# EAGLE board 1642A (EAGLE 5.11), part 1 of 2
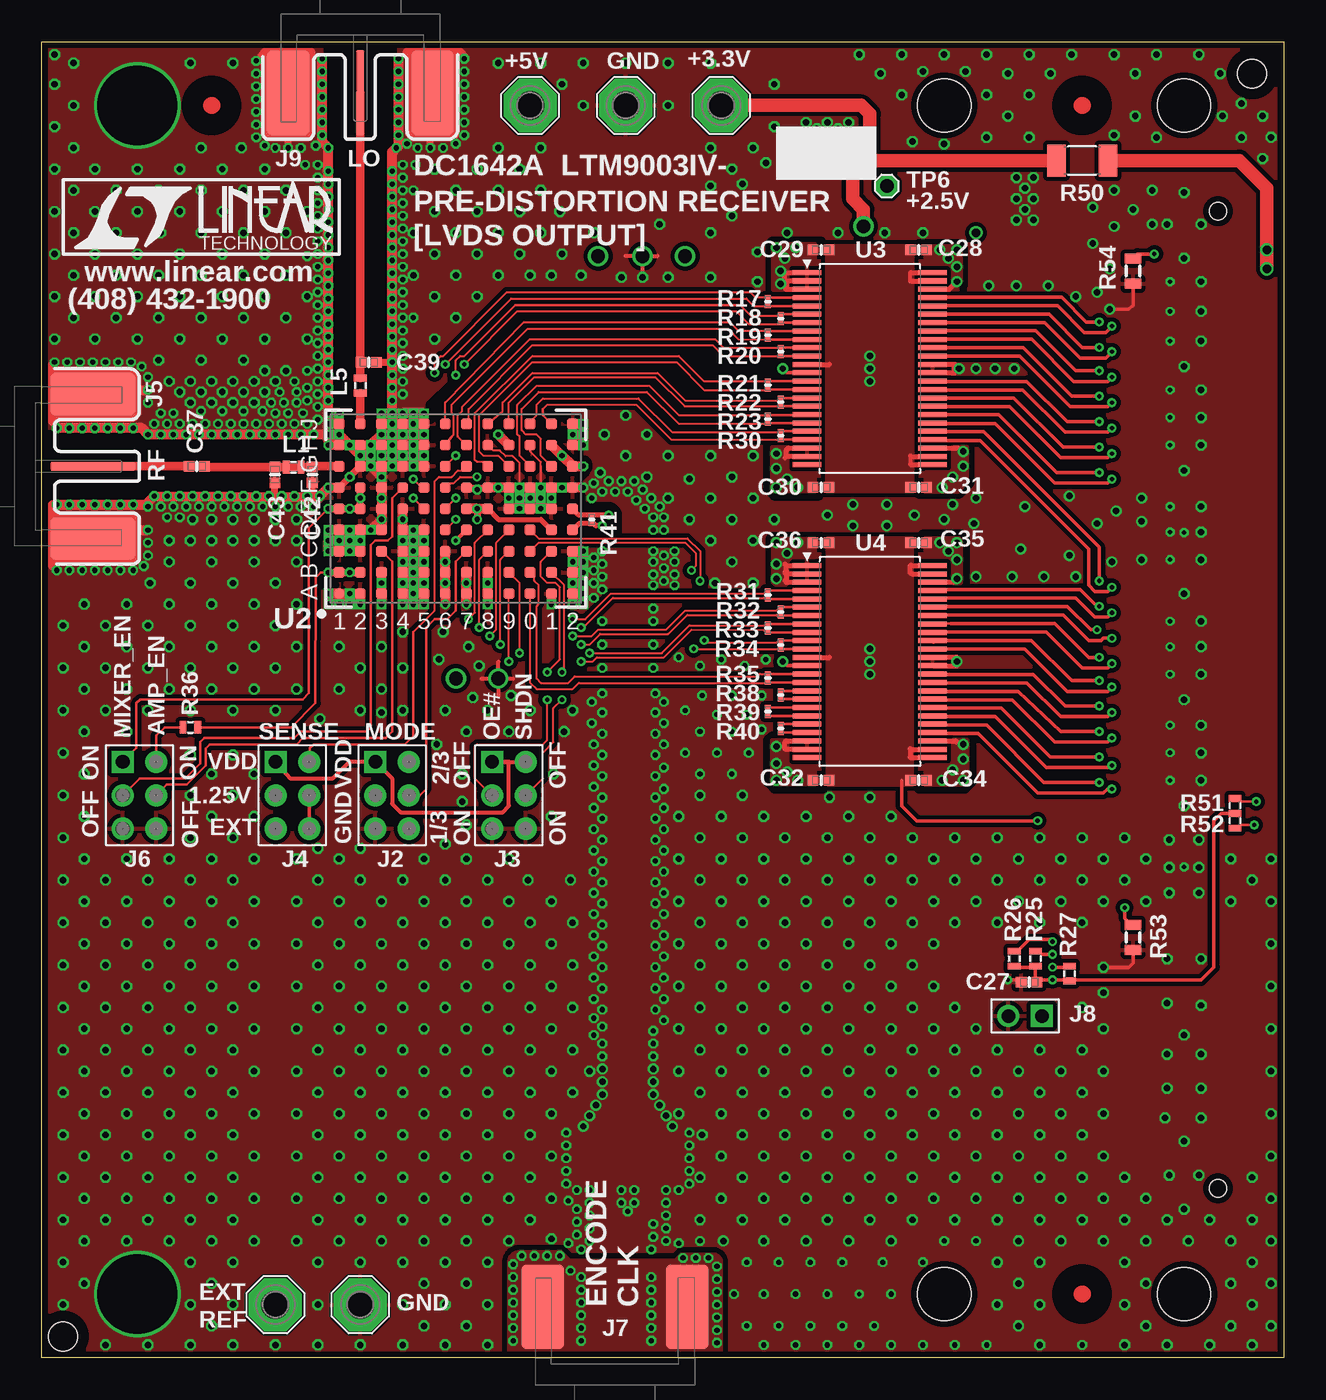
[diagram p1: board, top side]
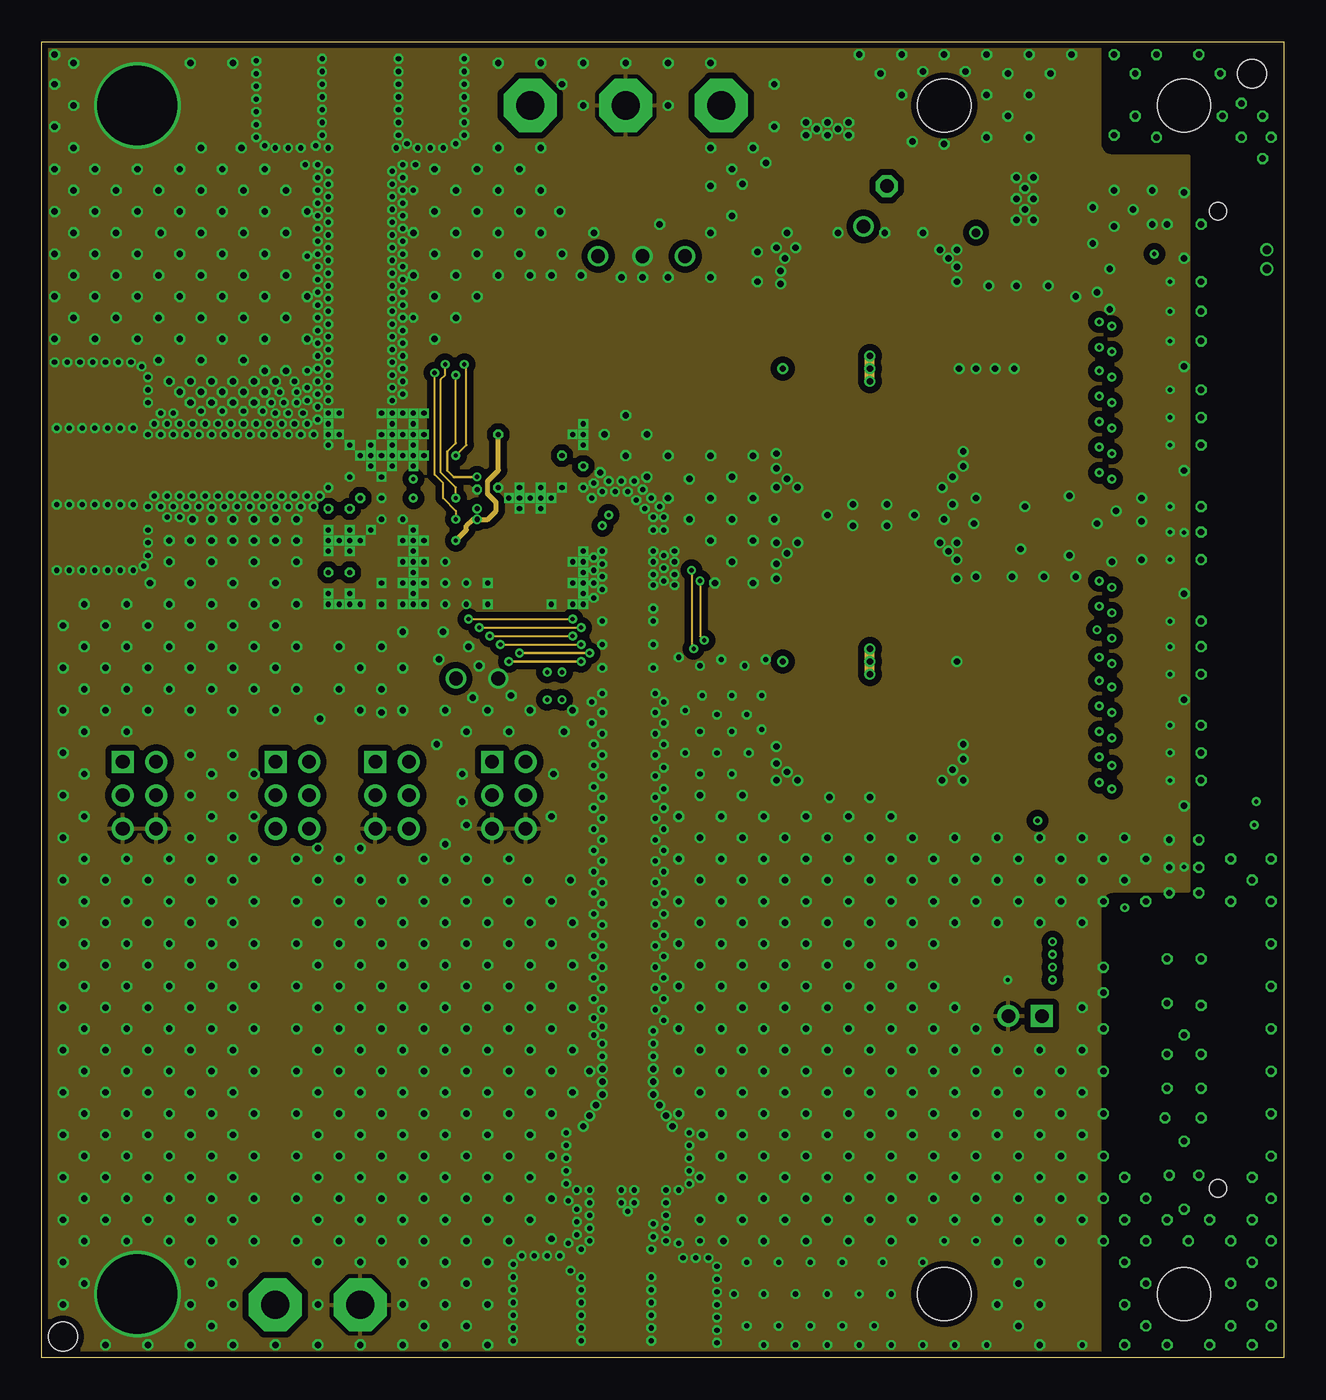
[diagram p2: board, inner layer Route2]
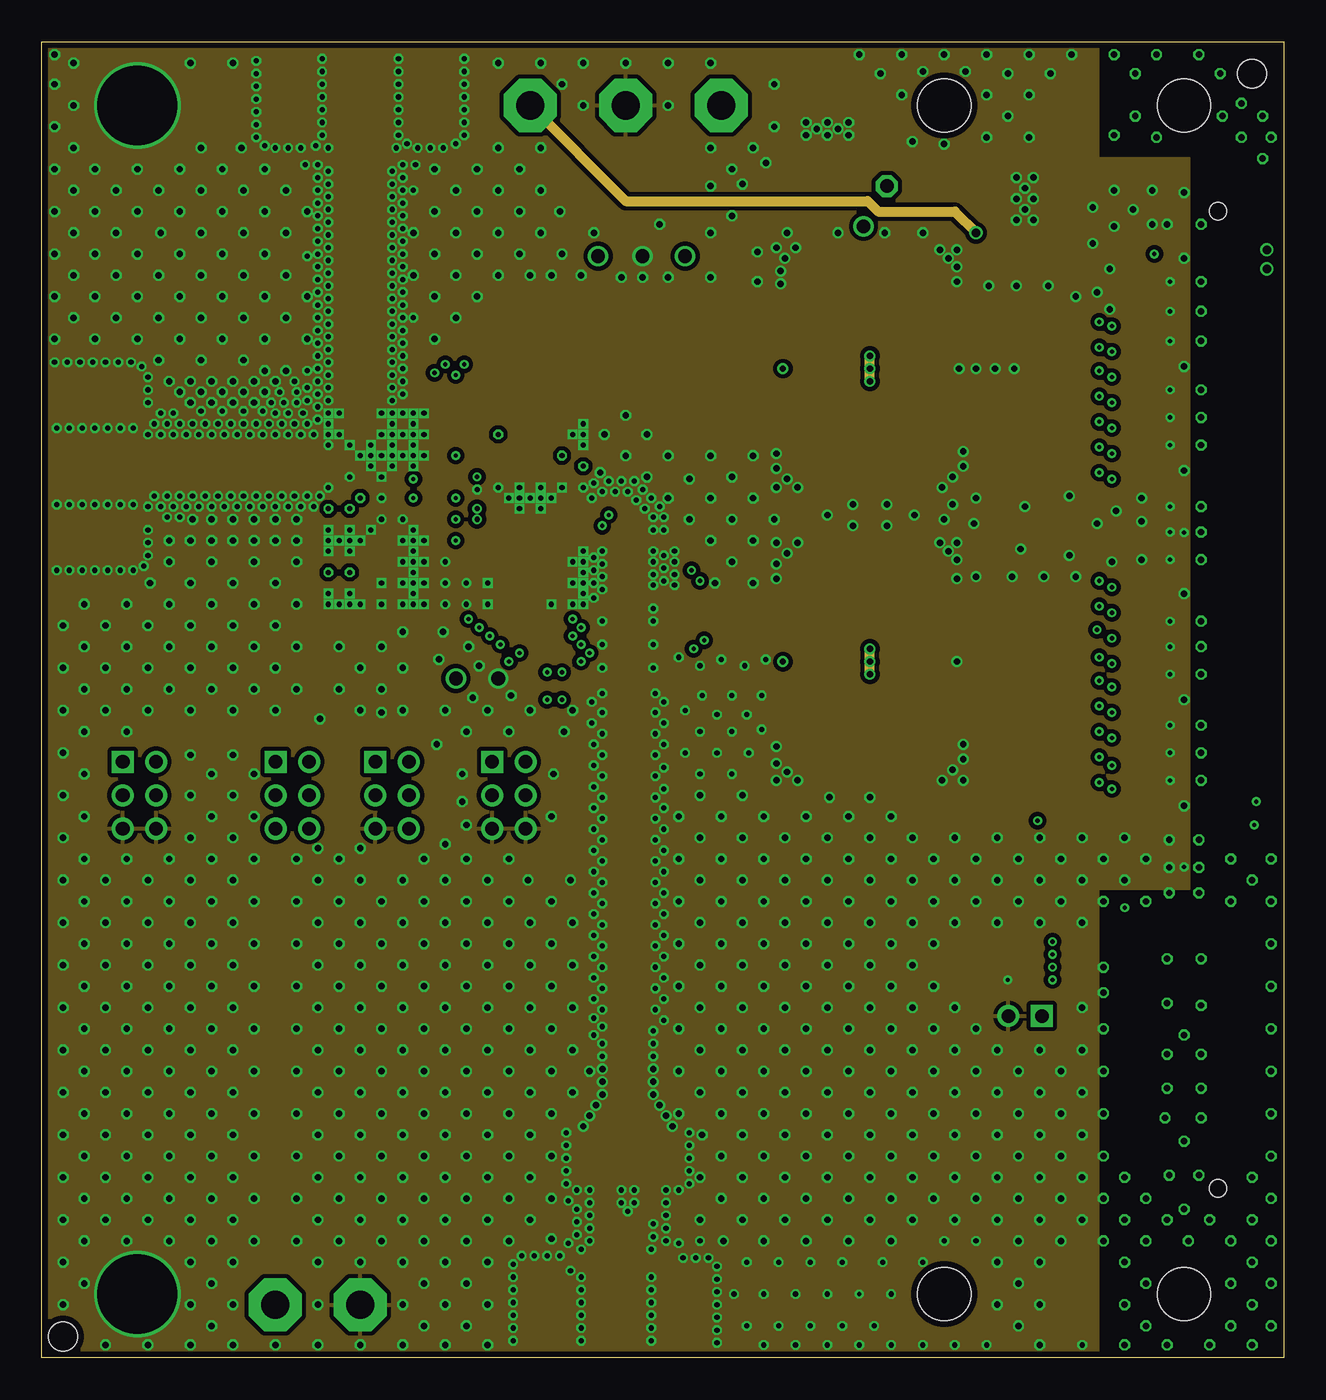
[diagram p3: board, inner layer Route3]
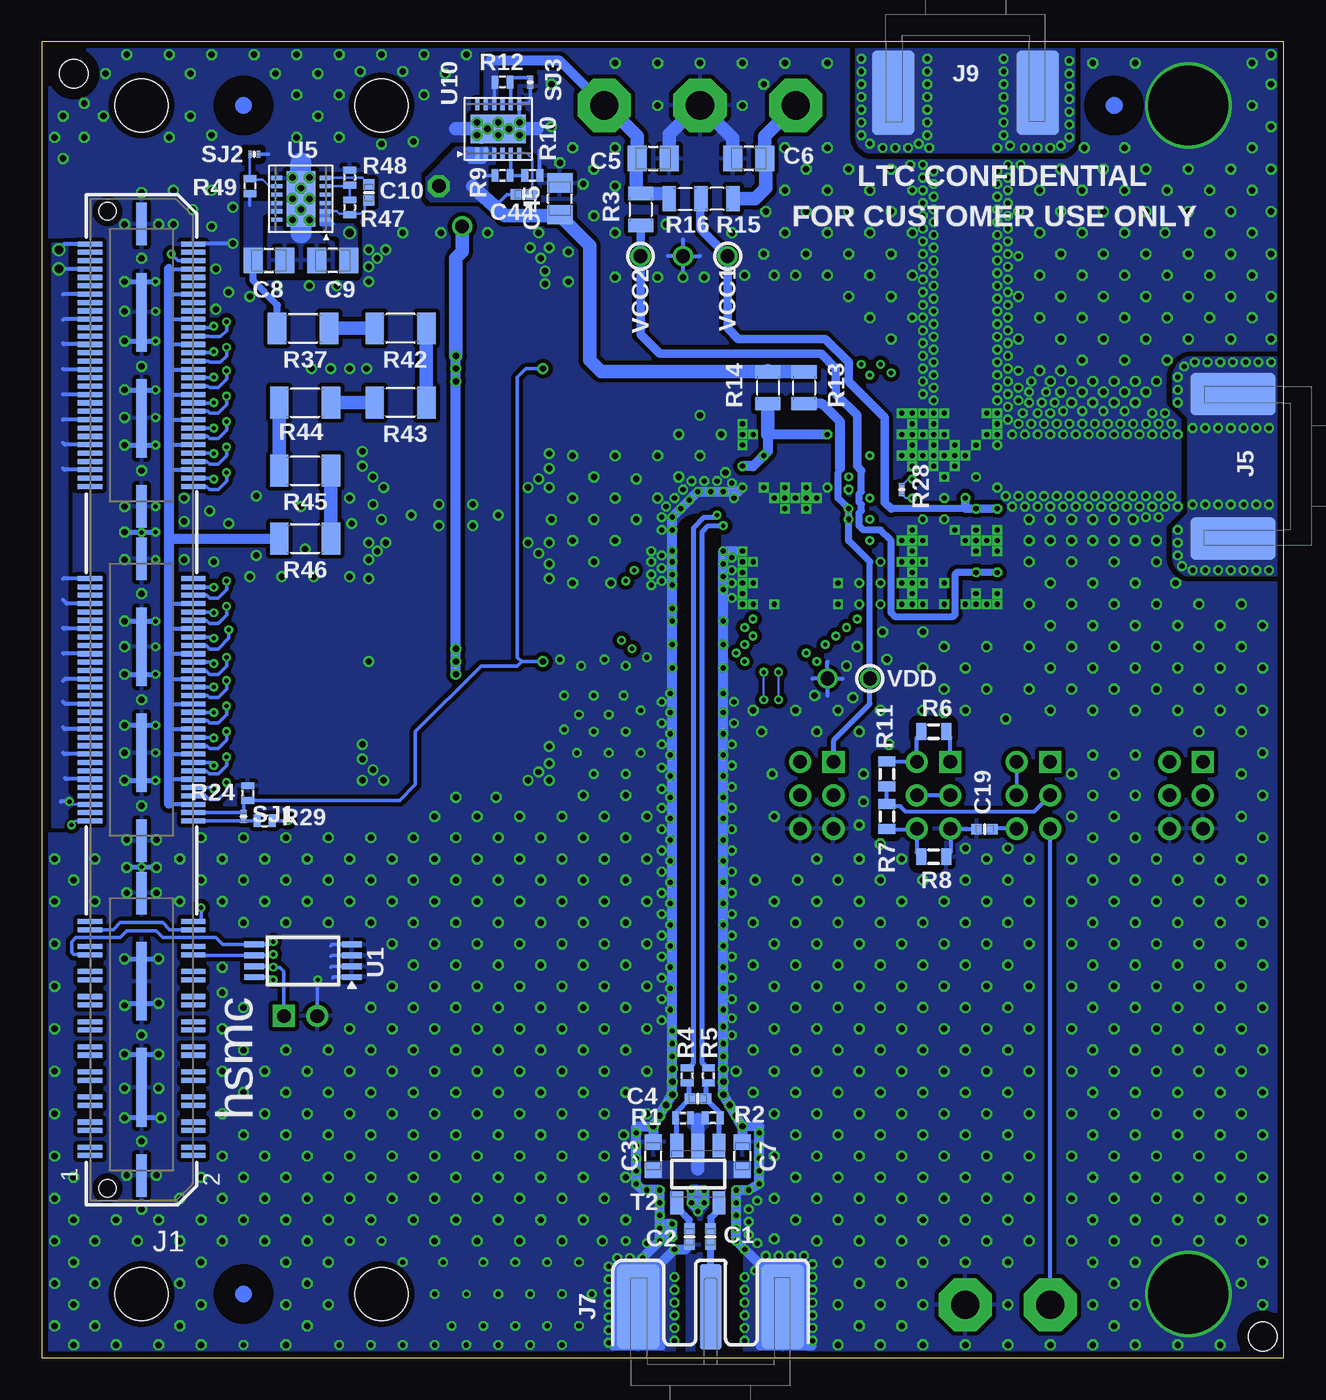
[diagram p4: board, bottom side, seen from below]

Size 74.3 x 78.74 mm. Coordinates in mm from the lower left corner, seen from the top.
Outline: 74.3,6.98 74.3,0 0,0 0,78.74 74.3,78.74 74.3,6.98
Outline: 74.3,6.98 74.3,6.73
Copper layers (1+2*3+16): Top 0.035mm / dielectric 0.28mm / Route2 0.035mm / dielectric 0.7mm / Route3 0.035mm / dielectric 0.28mm / Bottom 0.035mm
Design rules "tight_with_rnding_err_tol": minimum track width 5mil, minimum drill 10mil, track to track 5mil, track to pad 5mil, pad to pad 5mil, via to via 5mil, smd to smd 0mil, copper to edge 15mil, drill to drill 12mil, minimum pad ring 10mil, minimum via ring 0.1372mm, stop-mask expansion 3mil, vias tented up to drill 16mil, thermal gap 10mil
tRestrict: area 35.4,65.4 to 36.5,66.4; area 26.8,40.1 to 27.8,41.1; 96 lines
bRestrict: area 35.4,65.4 to 36.4,66.4; area 26.8,40.1 to 27.8,41.1; 56 lines

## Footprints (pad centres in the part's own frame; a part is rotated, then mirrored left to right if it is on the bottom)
C0402 = smd 0.635 x 0.635: 1 -0.472,0; 2 0.472,0
C0603 = smd 0.914 x 1.016: 1 -0.837,0; 2 0.837,0
C0805 = smd 1.143 x 1.524: 1 -0.952,0; 2 0.952,0
HSMC_ASP-122952-01_MEZZANINECARD = smd 0.305 x 1.448: 1 -27.271,3.086; 2 -27.271,-3.086; 3 -26.77,3.086; 4 -26.77,-3.086; 5 -25.77,3.086; 6 -25.77,-3.086; 7 -25.269,3.086; 8 -25.269,-3.086; 9 -24.268,3.086; 10 -24.268,-3.086; 11 -23.768,3.086; 12 -23.768,-3.086; 13 -22.767,3.086; 14 -22.767,-3.086; 15 -22.267,3.086; 16 -22.267,-3.086; 17 -21.266,3.086; 18 -21.266,-3.086; 19 -20.766,3.086; 20 -20.766,-3.086; 21 -19.765,3.086; 22 -19.765,-3.086; 23 -19.265,3.086; 24 -19.265,-3.086; 25 -18.264,3.086; 26 -18.264,-3.086; 27 -17.764,3.086; 28 -17.764,-3.086; 29 -16.763,3.086; 30 -16.763,-3.086; 31 -16.262,3.086; 32 -16.262,-3.086; 33 -15.262,3.086; 34 -15.262,-3.086; 35 -14.761,3.086; 36 -14.761,-3.086; 37 -13.76,3.086; 38 -13.76,-3.086; 39 -13.26,3.086; 40 -13.26,-3.086; 41 -7.255,3.086; 42 -7.255,-3.086; 43 -6.755,3.086; 44 -6.755,-3.086; 45 -6.255,3.086; 46 -6.255,-3.086; 47 -5.754,3.086; 48 -5.754,-3.086; 49 -5.254,3.086; 50 -5.254,-3.086; 51 -4.754,3.086; 52 -4.754,-3.086; 53 -4.253,3.086; 54 -4.253,-3.086; 55 -3.753,3.086; 56 -3.753,-3.086; 57 -3.252,3.086; 58 -3.252,-3.086; 59 -2.752,3.086; 60 -2.752,-3.086; 61 -2.252,3.086; 62 -2.252,-3.086; 63 -1.751,3.086; 64 -1.751,-3.086; 65 -1.251,3.086; 66 -1.251,-3.086; 67 -0.75,3.086; 68 -0.75,-3.086; 69 -0.25,3.086; 70 -0.25,-3.086; 71 0.25,3.086; 72 0.25,-3.086; 73 0.751,3.086; 74 0.751,-3.086; 75 1.251,3.086; 76 1.251,-3.086; 77 1.751,3.086; 78 1.751,-3.086; 79 2.252,3.086; 80 2.252,-3.086; 81 2.752,3.086; 82 2.752,-3.086; 83 3.252,3.086; 84 3.252,-3.086; 85 3.753,3.086; 86 3.753,-3.086; 87 4.253,3.086; 88 4.253,-3.086; 89 4.754,3.086; 90 4.754,-3.086; 91 5.254,3.086; 92 5.254,-3.086; 93 5.754,3.086; 94 5.754,-3.086; 95 6.255,3.086; 96 6.255,-3.086; 97 6.755,3.086; 98 6.755,-3.086; 99 7.255,3.086; 100 7.255,-3.086; 101 12.76,3.086; 102 12.76,-3.086; 103 13.26,3.086; 104 13.26,-3.086; 105 13.761,3.086; 106 13.761,-3.086; 107 14.261,3.086; 108 14.261,-3.086; 109 14.761,3.086; 110 14.761,-3.086; 111 15.262,3.086; 112 15.262,-3.086; 113 15.762,3.086; 114 15.762,-3.086; 115 16.262,3.086; 116 16.262,-3.086; 117 16.763,3.086; 118 16.763,-3.086; 119 17.263,3.086; 120 17.263,-3.086; 121 17.764,3.086; 122 17.764,-3.086; 123 18.264,3.086; 124 18.264,-3.086; 125 18.764,3.086; 126 18.764,-3.086; 127 19.265,3.086; 128 19.265,-3.086; 129 19.765,3.086; 130 19.765,-3.086; 131 20.265,3.086; 132 20.265,-3.086; 133 20.766,3.086; 134 20.766,-3.086; 135 21.266,3.086; 136 21.266,-3.086; 137 21.767,3.086; 138 21.767,-3.086; 139 22.267,3.086; 140 22.267,-3.086; 141 22.767,3.086; 142 22.767,-3.086; 143 23.268,3.086; 144 23.268,-3.086; 145 23.768,3.086; 146 23.768,-3.086; 147 24.268,3.086; 148 24.268,-3.086; 149 24.769,3.086; 150 24.769,-3.086; 151 25.269,3.086; 152 25.269,-3.086; 153 25.77,3.086; 154 25.77,-3.086; 155 26.27,3.086; 156 26.27,-3.086; 157 26.77,3.086; 158 26.77,-3.086; 159 27.271,3.086; 160 27.271,-3.086 | smd 2.54 x 0.635: G1 -28.461,0; G4 -11.57,0; G5 -8.445,0; G8 8.445,0; G9 11.57,0; G12 28.461,0 | smd 4.699 x 0.635: G2 -23.191,0; G3 -16.841,0; G6 -3.176,0; G7 3.174,0; G10 16.839,0; G11 23.189,0 | hole 3.175: -35.56,0; 35.56,0; -35.56,-14.351; 35.56,-14.351 | hole 1.016: -29.235,2.032; 29.235,2.032
HDR-3X2PS-2MM = drill 0.813 square: 1 -2,-1 | drill 0.813 round: 2 -2,1; 3 0,-1; 4 0,1; 5 2,-1; 6 2,1
SMA_FEMALE_EDGE_MNT_GHZ = smd 5.08 x 0.508: 1 3.048,0 | smd 5.08 x 2.54: 2 3.048,4.318; 3 3.048,-4.318 | smd 5.08 x 2.54 bottom: 4 3.048,4.318; 5 3.048,-4.318
SMA-FEMALE-EDGE-MNT = smd 5.08 x 1.27: 1 3.048,0 | smd 5.08 x 2.54: 2 3.048,4.318; 3 3.048,-4.318 | smd 5.08 x 2.54 bottom: 4 3.048,4.318; 5 3.048,-4.318
HDR-2X1PS-2MM = drill 0.813 square: 1 0,0 | drill 0.813 round: 2 2,0
L0402 = smd 0.406 x 0.762: 1 -0.447,0; 2 0.447,0
R0402 = smd 0.406 x 0.762: 1 -0.447,0; 2 0.447,0
R0805 = smd 0.8 x 1.5: 1 -0.951,0; 2 0.951,0
R0603 = smd 0.6 x 1: 1 -0.75,0; 2 0.75,0
R0201 = smd 0.279 x 0.432: 1 -0.254,0; 2 0.254,0
R1206 = smd 1.1 x 1.9: 1 -1.547,0; 2 1.547,0
SJ1 = smd 0.279 x 0.432: 1 -0.254,0; 2 0.254,0
MACOM_ETC1-XFMR = smd 0.762 x 1.397: 1 0,0; 2 1.27,0; 3 2.54,0; 4 2.54,-3.429; 5 0,-3.429
TURRET_MILLMAX_2308-2 = drill 1.676 pad 3.175 octagon: 1 0,0
VIA-25MIL = drill 0.813 pad 1.143 octagon: 1 0,0
TSSOP8 = smd 0.35 x 1.2: 1 -0.975,-2.925; 2 -0.325,-2.925; 3 0.325,-2.925; 4 0.975,-2.925; 5 0.975,2.925; 6 0.325,2.925; 7 -0.325,2.925; 8 -0.975,2.925
LTM9003-RNDED = smd 0.635 x 0.635: A1 -6.985,-5.08; A2 -5.715,-5.08; A3 -4.445,-5.08; A4 -3.175,-5.08; A5 -1.905,-5.08; A6 -0.635,-5.08; A7 0.635,-5.08; A8 1.905,-5.08; A9 3.175,-5.08; A10 4.445,-5.08; A11 5.715,-5.08; A12 6.985,-5.08; B1 -6.985,-3.81; B2 -5.715,-3.81; B3 -4.445,-3.81; B4 -3.175,-3.81; B5 -1.905,-3.81; B6 -0.635,-3.81; B7 0.635,-3.81; B8 1.905,-3.81; B9 3.175,-3.81; B10 4.445,-3.81; B11 5.715,-3.81; B12 6.985,-3.81; C1 -6.985,-2.54; C2 -5.715,-2.54; C3 -4.445,-2.54; C4 -3.175,-2.54; C5 -1.905,-2.54; C6 -0.635,-2.54; C7 0.635,-2.54; C8 1.905,-2.54; C9 3.175,-2.54; C10 4.445,-2.54; C11 5.715,-2.54; C12 6.985,-2.54; D1 -6.985,-1.27; D2 -5.715,-1.27; D3 -4.445,-1.27; D4 -3.175,-1.27; D5 -1.905,-1.27; D6 -0.635,-1.27; D7 0.635,-1.27; D8 1.905,-1.27; D9 3.175,-1.27; D10 4.445,-1.27; D11 5.715,-1.27; D12 6.985,-1.27; E1 -6.985,0; E2 -5.715,0; E3 -4.445,0; E4 -3.175,0; E5 -1.905,0; E6 -0.635,0; E7 0.635,0; E8 1.905,0; E9 3.175,0; E10 4.445,0; E11 5.715,0; E12 6.985,0; F1 -6.985,1.27; F2 -5.715,1.27; F3 -4.445,1.27; F4 -3.175,1.27; F5 -1.905,1.27; F6 -0.635,1.27; F7 0.635,1.27; F8 1.905,1.27; F9 3.175,1.27; F10 4.445,1.27; F11 5.715,1.27; F12 6.985,1.27; G1 -6.985,2.54; G2 -5.715,2.54; G3 -4.445,2.54; G4 -3.175,2.54; G5 -1.905,2.54; G6 -0.635,2.54; G7 0.635,2.54; G8 1.905,2.54; G9 3.175,2.54; G10 4.445,2.54; G11 5.715,2.54; G12 6.985,2.54; H1 -6.985,3.81; H2 -5.715,3.81; H3 -4.445,3.81; H4 -3.175,3.81; H5 -1.905,3.81; H6 -0.635,3.81; H7 0.635,3.81; H8 1.905,3.81; H9 3.175,3.81; H10 4.445,3.81; H11 5.715,3.81; H12 6.985,3.81; J1 -6.985,5.08; J2 -5.715,5.08; J3 -4.445,5.08; J4 -3.175,5.08; J5 -1.905,5.08; J6 -0.635,5.08; J7 0.635,5.08; J8 1.905,5.08; J9 3.175,5.08; J10 4.445,5.08; J11 5.715,5.08; J12 6.985,5.08
TSSOP48 = smd 0.3 x 1.7: 1 -5.75,-3.75; 2 -5.25,-3.75; 3 -4.75,-3.75; 4 -4.25,-3.75; 5 -3.75,-3.75; 6 -3.25,-3.75; 7 -2.75,-3.75; 8 -2.25,-3.75; 9 -1.75,-3.75; 10 -1.25,-3.75; 11 -0.75,-3.75; 12 -0.25,-3.75; 13 0.25,-3.75; 14 0.75,-3.75; 15 1.25,-3.75; 16 1.75,-3.75; 17 2.25,-3.75; 18 2.75,-3.75; 19 3.25,-3.75; 20 3.75,-3.75; 21 4.25,-3.75; 22 4.75,-3.75; 23 5.25,-3.75; 24 5.75,-3.75; 25 5.75,3.75; 26 5.25,3.75; 27 4.75,3.75; 28 4.25,3.75; 29 3.75,3.75; 30 3.25,3.75; 31 2.75,3.75; 32 2.25,3.75; 33 1.75,3.75; 34 1.25,3.75; 35 0.75,3.75; 36 0.25,3.75; 37 -0.25,3.75; 38 -0.75,3.75; 39 -1.25,3.75; 40 -1.75,3.75; 41 -2.25,3.75; 42 -2.75,3.75; 43 -3.25,3.75; 44 -3.75,3.75; 45 -4.25,3.75; 46 -4.75,3.75; 47 -5.25,3.75; 48 -5.75,3.75
DE12 = smd 0.25 x 0.65: 1 -1.25,-1.45; 2 -0.75,-1.45; 3 -0.25,-1.45; 4 0.25,-1.45; 5 0.75,-1.45; 6 1.25,-1.45; 7 1.25,1.45; 8 0.75,1.45; 9 0.25,1.45; 10 -0.25,1.45; 11 -0.75,1.45; 12 -1.25,1.45 | smd 3.3 x 1.7: GP 0,0
TOOLING_HOLE_0R067 = hole 1.702: 0,0

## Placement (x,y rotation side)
C1  0.01uF  [C0402]  34.29,7.24 90 bottom
C2  0.01uF  [C0402]  35.56,7.24 90 bottom
C3  0.1uF  [C0603]  37.72,12.06 90 bottom
C4  8.2pF  [C0402]  35.05,15.49 0 bottom
C5  4.7uF  [C0805]  37.72,71.75 0 bottom
C6  4.7uF  [C0805]  32,71.75 180 bottom
C7  0.1uF  [C0603]  32.38,12.06 90 bottom
C8  4.7uF  [C0805]  60.71,65.66 0 bottom
C9  4.7uF  [C0805]  56.9,65.66 180 bottom
C10  0.01uF  [C0402]  54.74,69.72 90 bottom
C19  0.1uF  [C0402]  17.91,31.62 180 bottom
C27  0.1uF  [C0402]  59.05,22.48 180 top
C28  0.1uF  [C0402]  52.45,66.29 0 top
C29  0.1uF  [C0402]  46.61,66.29 180 top
C30  0.1uF  [C0402]  46.61,52.07 180 top
C31  0.1uF  [C0402]  52.45,52.07 0 top
C32  0.1uF  [C0402]  46.61,34.54 180 top
C34  0.1uF  [C0402]  52.45,34.54 0 top
C35  0.1uF  [C0402]  52.45,48.77 0 top
C36  0.1uF  [C0402]  46.61,48.77 180 top
C37  DNI  [C0402]  9.27,53.34 180 top
C39  DNI  [C0402]  19.56,59.56 0 top
C42  DNI  [C0402]  16.18,52.83 270 top
C43  DNI  [C0402]  13.94,52.83 270 top
C44  0.01uF  [C0402]  45.47,69.6 0 bottom
C45  10uF  [C0805]  43.31,69.34 90 bottom
J1  ALTERA_HSME_DE_CARD  [HSMC_ASP-122952-01_MEZZANINECARD]  68.33,39.37 90 bottom
J2  2802S-06G2  [HDR-3X2PS-2MM]  20.95,33.66 270 top
J3  2802S-06G2  [HDR-3X2PS-2MM]  27.94,33.66 270 top
J4  2802S-06G2  [HDR-3X2PS-2MM]  14.99,33.66 270 top
J5  SMA  [SMA_FEMALE_EDGE_MNT_GHZ]  0,53.34 0 top
J6  2802S-06G2  [HDR-3X2PS-2MM]  5.84,33.66 270 top
J7  SMA  [SMA-FEMALE-EDGE-MNT]  34.29,0 90 bottom
J8  JMPR-2X1-PS-2MM  [HDR-2X1PS-2MM]  59.82,20.45 180 top
J9  SMA  [SMA_FEMALE_EDGE_MNT_GHZ]  19.05,78.74 270 top
L1  DNI  [L0402]  15.06,53.29 0 top
L5  DNI  [L0402]  19.05,58.17 270 top
R1  49.9  [R0402]  35.94,14.35 0 bottom
R2  49.9  [R0402]  34.16,14.35 180 bottom
R3  0  [R0805]  38.48,68.71 270 bottom
R4  4.99  [R0402]  35.69,16.89 90 bottom
R5  4.99  [R0402]  34.42,16.89 90 bottom
R6  1000  [R0603]  20.95,37.47 180 bottom
R7  499  [R0603]  23.75,32.38 90 bottom
R8  1000  [R0603]  20.95,29.97 0 bottom
R9  64.9K  [R0402]  46.74,70.74 180 bottom
R10  100K  [R0402]  44.96,70.74 180 bottom
R11  499  [R0603]  23.75,34.93 90 bottom
R12  10K  [R0402]  46.74,76.33 180 bottom
R13  0  [R0805]  28.7,58.04 270 bottom
R14  0  [R0805]  30.86,58.04 270 bottom
R15  DNI  [R0805]  33.91,69.34 180 bottom
R16  0  [R0805]  35.81,69.34 0 bottom
R17  100  [R0201]  43.43,63.2 270 top
R18  100  [R0201]  44.2,62.18 270 top
R19  100  [R0201]  43.43,61.19 270 top
R20  100  [R0201]  44.2,60.2 270 top
R21  100  [R0201]  43.43,58.19 270 top
R22  100  [R0201]  44.2,57.18 270 top
R23  100  [R0201]  43.43,56.16 270 top
R24  100K  [R0402]  61.98,33.78 270 bottom
R25  4990  [R0402]  59.44,23.88 270 top
R26  4990  [R0402]  58.17,23.88 270 top
R27  4990  [R0402]  61.47,22.99 270 top
R28  100  [R0201]  22.86,51.94 270 bottom
R29  4990  [R0402]  60.96,32.13 0 bottom
R30  100  [R0201]  44.2,55.17 270 top
R31  100  [R0201]  43.43,45.64 270 top
R32  100  [R0201]  44.2,44.63 270 top
R33  100  [R0201]  43.43,43.66 270 top
R34  100  [R0201]  44.2,42.65 270 top
R35  100  [R0201]  43.43,40.67 270 top
R36  4990  [R0402]  8.89,37.72 0 top
R37  10  [R1206]  58.67,61.6 0 bottom
R38  100  [R0201]  44.2,39.65 270 top
R39  100  [R0201]  43.43,38.66 270 top
R40  100  [R0201]  44.2,37.64 270 top
R41  DNI  [R0201]  32.89,50.17 270 top
R42  10  [R1206]  52.83,61.6 180 bottom
R43  10  [R1206]  52.83,57.15 180 bottom
R44  10  [R1206]  58.55,57.15 0 bottom
R45  10  [R1206]  58.55,53.09 0 bottom
R46  10  [R1206]  58.55,49.02 0 bottom
R47  32.4K  [R0402]  55.88,68.83 270 bottom
R48  100K  [R0402]  55.88,70.61 270 bottom
R49  10K  [R0402]  61.85,70.1 270 bottom
R50  0  [R1206]  62.23,71.63 180 top
R51  4.99  [R0402]  71.37,33.02 90 top
R52  DNP  [R0402]  71.37,32.13 90 top
R53  1000  [R0603]  65.28,25.15 270 top
R54  1000  [R0603]  65.28,65.02 90 top
SJ1  SOLDER_JMPR-1  [SJ1]  62.23,32.38 90 bottom
SJ2  SOLDER_JMPR-1  [SJ1]  61.6,72.01 0 bottom
SJ3  SOLDER_JMPR-1  [SJ1]  45.09,76.33 270 bottom
T2  MABA-007159-000000  [MACOM_ETC1-XFMR]  36.32,12.7 0 bottom
TP1  TURRET0.063  [TURRET_MILLMAX_2308-2]  13.97,3.17 0 top
TP2  TURRET0.063  [TURRET_MILLMAX_2308-2]  19.05,3.17 0 top
TP3  TURRET0.063  [TURRET_MILLMAX_2308-2]  40.64,74.93 180 top
TP4  TURRET0.063  [TURRET_MILLMAX_2308-2]  34.93,74.93 0 top
TP5  TURRET0.063  [TURRET_MILLMAX_2308-2]  29.21,74.93 0 top
TP6  TSTPNT25MIL  [VIA-25MIL]  50.55,70.1 0 top
U1  24LC02ST  [TSSOP8]  58.67,23.75 90 bottom
U2  LTM9003IV-xx  [LTM9003-RNDED]  24.77,50.8 0 top
U3  FIN1108  [TSSOP48]  49.53,59.18 270 top
U4  FIN1108  [TSSOP48]  49.53,41.66 270 top
U5  LT1763CDE  [DE12]  58.8,69.34 90 bottom
U10  LT1763CDE  [DE12]  46.99,73.53 0 bottom
U$2  [TOOLING_HOLE_0R067]  72.39,76.83 0 top
U$3  [TOOLING_HOLE_0R067]  1.27,1.27 0 top
U$4  [FIDUCIAL_0R040]  10.16,74.93 0 top
U$5  [FIDUCIAL_0R040]  62.23,74.93 0 top
U$6  [FIDUCIAL_0R040]  62.23,3.81 0 top
U$7  [LT-LOGO]  1.27,66.04 0 top
U$8  [LETTER_L]  not placed on the board
U$9  [REVISION-HISTORY]  not placed on the board
U$10  [ANSI-DOC-FIELD]  not placed on the board
U$11  [STACKUP-4LAYER,1CORE]  not placed on the board
U$12  [FAB-NOTES-AU-THERMAL]  not placed on the board
U$13  [ARTWORK_TITLEBLOCK]  not placed on the board

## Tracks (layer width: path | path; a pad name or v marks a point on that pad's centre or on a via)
3.3VHOST  (via drill 0.25, 0.51)
  Top 0.152: R51.2 71.44,33.4 71.63,33.4 71.75,33.27 v72.64,33.27
  Top 0.813: R50.1 71.63,71.63 73.28,69.98 v73.28,66.29 v73.28,65.15
  Bottom 0.152: J1.45 72.48,33.12 v72.64,33.27
  Bottom 0.254: J1.159 72.93,66.64 73.02,66.55 | J1.153 73.01,65.14 73.02,65.15 | J1.147 73.01,63.64 73.02,63.63 | J1.141 72.99,62.14 73.02,62.1 | J1.135 72.95,60.64 73.02,60.71 | J1.129 72.98,59.14 73.02,59.18 | J1.123 73,57.63 73.02,57.66 | J1.117 73.02,56.13 | J1.111 72.92,54.63 73.02,54.74 | J1.105 72.94,53.13 73.02,53.21 | J1.99 73.01,46.62 73.02,46.61 | J1.93 72.81,45.12 73.02,45.34 | J1.87 72.96,43.62 73.02,43.69 | J1.81 72.98,42.12 73.02,42.16 | J1.75 72.92,40.62 73.02,40.51 | J1.69 72.9,39.12 73.02,39.24 | J1.63 72.92,37.62 73.02,37.72 | J1.57 72.95,36.12 73.02,36.2 | J1.51 72.84,34.62 72.9,34.67 | v72.64,33.27 73.15,33.27
  pour Bottom: 72.77,66.67 72.77,33.78 72.52,33.53 72.52,33.02 72.77,32.77 72.77,31.75 73.66,31.75 73.66,66.67
+2.5V
  Bottom 0.203: 47.24,70.87 47.12,70.74 R9.2 47.75,70.74 | 45.85,69.6 C44.1 46.48,69.6 47.12,68.96 47.88,69.72
  Bottom 0.254: 47.24,72.26 U10.3 | C45.1 42.93,68.01 42.93,67.94
  Bottom 0.406: 47.75,72.01 47.75,72.26 48.77,72.26 48.77,71.88 47.88,71.88 47.88,71.63 48.64,71.63
  Bottom 0.813: R13.1 30.8,58.99 30.86,59.05 R14.1 40.83,58.99 41.53,59.69 41.53,66.55 42.93,67.94 43.31,68.33 46.61,68.33 46.99,68.71 48.13,69.72 48.51,70.1
  pour Bottom (no thermals): 47.17,72.34 47.22,72.39 49.53,72.39 51.31,70.61 51.31,69.47 51.05,69.21 47.88,69.21 47.62,69.47 47.62,71.32 47.5,71.45 47.17,71.45
+3.3V  (via drill 0.25, 0.38, 0.81)
  Top 0.203: v59.56,32.13 52.32,32.13 51.44,33.02 51.44,34.54
  Top 0.254: 47.11,59.43 47.12,59.44 | 51.98,64.93 51.94,64.9 51.94,64.39 51.99,64.43 | 51.94,53.98 51.99,53.93 51.99,53.51 51.94,53.47 51.98,53.43
  Top 0.305: U3.12 47.11,59.43 | 51.98,64.93 U3.48 | 51.99,64.43 U3.47 | 51.99,53.93 U3.26 | 51.98,53.43 U3.25 | U4.48 51.98,47.41 51.94,47.37 51.94,46.99 52.03,46.91 U4.47 | U4.12 47.11,41.91 47.12,41.91 | U4.25 51.98,35.91 51.94,35.94 51.94,36.45 51.99,36.41 U4.26
  Top 0.813: v49.15,67.69 49.15,68.71 48.51,69.34 48.51,70.87 49.53,71.88 | TP3.1 49.02,74.93 49.53,74.42 49.53,71.88 | R50.2 49.53,71.63 49.53,71.88
  Route2 0.61: v49.53,58.42 v49.53,59.94 | v49.53,40.89 v49.53,42.42
  Route3 0.61: v49.53,58.42 v49.53,59.94 | v49.53,40.89 v49.53,42.42
  Bottom 0.203: R12.2 47.12,76.33 47.24,76.2 U10.10 | v59.56,32.13 R29.2
  Bottom 0.61: TP3.1 43.31,77.6 47.5,77.6 | v49.53,40.89 v49.53,41.66 v49.53,42.42 v49.53,58.42 v49.53,59.18 v49.53,59.94
  Bottom 0.813: TP3.1 40.64,75.06 38.67,73.09 C5.1 38.74,71.75 38.74,69.66 R3.1 37.02,69.66 36.77,69.4 R16.1 | v49.53,59.94 49.53,65.79 49.15,66.17 v49.15,67.69
  pour Top (no thermals): 52.07,66.55 52.07,51.82 46.99,51.82 46.99,66.55
  pour Top (isolate 0.254, no thermals): 46.99,49.02 46.99,34.29 52.07,34.29 52.07,49.02
  pour Bottom (no thermals): 47.8,74.73 47.8,77.83 47.04,77.83 47.04,75.49 47.19,75.34 47.19,74.73
+5V  (via drill 0.51)
  Route3 0.61: v55.88,67.31 54.61,68.58 50.04,68.58 49.4,69.21 34.93,69.21 TP5.1
  Bottom 0.152: U5.2 56.65,68.59 56.52,68.45 55.88,68.45 R47.2 55.75,68.45 55.25,68.45 54.99,68.71 54.99,68.96 54.74,69.21 C10.1 | 57.61,68.43 57.61,67.77 56.92,67.77 56.82,67.87 57.1,68.15 57.1,68.4 57.33,68.4
  Bottom 0.406: 57.33,68.4 57.33,67.89 57.12,67.89
  Bottom 0.813: TP5.1 31.05,73.09 C6.1 30.99,71.75 30.99,69.98 31.62,69.34 R15.1
  pour Bottom (no thermals): 57.61,69.16 57.61,67.77 57.02,67.18 56.64,67.18 56.44,66.98 56.44,64.97 55.45,64.97 55.45,67.54 55.7,67.79 56.74,67.79 57.1,68.15 57.1,69.16
+12V
  Bottom 0.254: J1.46 66.64,33.12 66.67,33.15 | J1.154 66.66,65.14 66.67,65.15 | J1.148 66.66,63.64 66.67,63.63 | J1.142 66.64,62.14 66.67,62.1 | J1.136 66.62,60.64 66.67,60.58 | J1.130 66.59,59.14 66.67,59.05 | J1.124 66.65,57.63 66.67,57.66 | J1.118 66.67,56.13 | J1.112 66.65,54.63 66.67,54.61 | J1.106 66.63,53.13 66.67,53.09 | J1.94 66.64,45.12 66.67,45.09 | J1.88 66.61,43.62 66.67,43.56 | J1.82 66.63,42.12 66.67,42.16 | J1.76 66.66,40.62 66.67,40.64 | J1.70 66.67,39.12 | J1.64 66.65,37.62 66.67,37.59 | J1.58 66.62,36.12 66.67,36.07 | J1.52 66.6,34.62 66.67,34.54
  Bottom 0.61: 66.67,33.15 66.67,34.54 66.67,36.07 66.67,37.59 66.67,39.12 66.67,40.64 66.67,42.16 66.67,43.56 66.67,45.09 66.67,49.02 | 66.67,49.02 66.67,53.09 66.67,54.61 66.67,56.13 66.67,57.66 66.67,59.05 66.67,60.58 66.67,62.1 66.67,63.63 66.67,65.15 | 66.67,49.02 R46.1
AMP_EN
  Top 0.152: U2.C3 20.95,47.62 20.95,37.47 20.57,37.08 15.62,37.08 15.24,36.7 10.06,36.7 9.8,36.45 9.8,35.43 8.66,34.29 7.48,34.29 J6.4
ECCN  (via drill 0.25)
  Top 0.305: v33.91,50.42 R41.1 32.13,50.42 U2.E12
  Bottom 0.305: R4.2 35.62,17.34 35.31,17.65 35.31,49.66 34.67,50.29 34.04,50.29 v33.91,50.42
ENCP  (via drill 0.25)
  Top 0.305: v33.53,49.78 33.15,49.78 33.02,49.91 R41.2 32.13,49.91 U2.D12
  Bottom 0.305: R5.2 34.48,17.34 34.8,17.65 34.8,49.4 34.42,49.78 v33.53,49.78
EXT_REF
  Bottom 0.254: J4.5 13.97,31.62 TP1.1
GND  (via drill 0.25, 0.3, 0.38, 0.81, 4.78)
  Top 0.127: U2.H10 29.21,54.23 29.84,53.59 29.84,53.34 | U2.H8 27,54.28 27.41,54.28 27.74,53.95 28.17,53.95 28.57,53.54 v28.57,52.07
  Top 0.152: v29.84,52.07 29.84,53.34
  Top 0.203: C27.2 58.46,22.61 v57.79,22.61 | R53.2 65.28,23.62 65.02,23.37 v63.5,23.37 | R54.1 65.28,62.99 65.02,62.74 v63.88,62.74
  Top 0.254: v35.94,65.91 34.93,65.91 | v35.94,65.91 36.83,65.91 | v35.94,65.91 35.94,66.8 | v35.94,64.64 v35.94,65.91 | 26.29,40.64 v27.3,40.64 | v27.3,40.64 28.19,40.64 | v27.3,40.64 27.3,41.66 | v27.3,40.64 27.3,39.62
  Top 0.305: U3.27 54.79,54.43 v55.12,54.23 | U3.23 44.53,53.93 | 44.53,53.93 44.45,53.85 | 44.53,53.93 44.53,54.31 44.65,54.43 U3.22 | U3.1 44.49,64.93 44.45,64.9 44.45,64.52 44.53,64.43 | U3.2 44.53,64.43 | 44.53,64.43 44.53,64.09 44.45,64.01 44.53,63.93 U3.3 | 44.54,47.41 U4.1 | 44.54,47.41 44.45,47.5 | 44.54,47.41 44.54,47.08 44.45,46.99 44.53,46.91 | U4.2 44.53,46.91 | 44.53,46.91 44.53,46.57 44.45,46.48 44.53,46.41 U4.3 | U4.46 54.53,46.41 54.61,46.48 | U4.23 44.49,36.41 44.45,36.45 44.45,36.83 44.53,36.91 U4.22 | U4.27 54.66,36.91 54.74,36.83 | U3.46 54.28,63.93 v54.74,64.39 | U3.36 54.61,58.93 54.61,59.44 53.21,59.44 | U4.36 53.34,41.41 53.34,41.4 54.74,41.4 54.74,41.91 53.21,41.91 | 25.53,51.94 v26.04,51.94 26.54,51.94 U2.F8 U2.F7 25.53,51.94
  Top 0.406: U2.F1 U2.G2 | v15.11,51.56 13.95,51.56 C43.2 | C42.2 16.18,51.51 v15.88,51.56 | C39.2 v20.95,59.56 | J9.4 23.24,75.69 v23.24,72.39 | v14.73,72.39 J9.5
  Top 0.508: v12.83,77.6 12.95,77.6 13.33,78.1 | 13.33,78.1 16.13,78.1 16.13,73.28 15.88,73.02 13.59,73.02 13.33,73.28 13.33,78.1 | v25.27,77.72 25.27,77.85 25.02,78.1 24.77,78.1 | 24.77,78.1 21.84,78.1 21.84,77.98 21.97,77.85 21.97,73.28 22.22,73.02 24.51,73.02 24.77,73.28 24.77,78.1 | v0.76,59.56 0.64,59.44 0.64,59.05 | 0.64,59.05 0.64,56.01 0.89,56.26 5.46,56.26 5.71,56.52 5.71,58.67 5.33,59.05 0.64,59.05 | v0.89,51.05 0.64,51.05 0.64,50.42 | 0.64,50.42 0.64,47.37 0.89,47.62 5.46,47.62 5.71,47.88 5.71,50.17 5.46,50.42 0.64,50.42
  Top 0.61: U2.F1 v17.14,52.07 v16.64,51.56 16.18,51.51 v6.73,51.56 6.22,51.05 v0.89,51.05 | v17.78,55.25 U2.J1 | U2.H1 v17.78,55.25 | v18.41,54.61 U2.H1 | U2.H2 v18.41,54.61 | v19.05,53.98 U2.H2 | v19.05,53.98 U2.G2 v19.68,53.34 | U2.H2 v19.68,54.61 | v19.68,54.61 U2.H3 | v20.32,53.98 U2.H3 | v19.68,53.98 v19.68,54.61 | U2.G3 v20.32,53.98 | v19.68,53.34 U2.G3 | v19.68,53.34 v19.68,53.98 | v19.68,53.98 v19.68,54.61 | v20.32,55.25 U2.J3 | U2.H3 v20.32,55.25 | U2.G3 v20.32,52.71 | v20.32,52.71 U2.F3 v20.32,51.44 U2.E3 v20.32,50.17 | v20.32,50.17 U2.D3 v19.68,49.53 | v19.68,49.53 U2.D2 | U2.D2 v18.41,49.53 | v18.41,49.53 U2.D1 | U2.D1 v17.14,49.53 v17.14,48.9 | v17.14,48.9 v17.14,48.26 U2.C1 | v17.78,48.9 U2.C1 | v17.78,48.9 v17.14,48.9 | v18.41,48.9 v17.78,48.9 | v18.41,48.9 18.41,49.02 | v18.41,48.9 v18.41,48.26 | U2.C1 U2.C2 v19.05,48.9 | U2.D2 v19.05,48.9 | v19.05,48.9 v18.41,48.9 | v18.41,49.53 v18.41,48.9 | U2.D1 v17.78,48.9 | v17.14,55.25 v17.14,55.88 | v17.14,55.25 v17.14,54.61 U2.H1 | v17.78,55.25 v17.14,55.25 | U2.J1 v17.14,55.88 | U2.J1 v17.78,56.52 v17.14,56.52 | v17.14,55.88 v17.14,56.52 | v18.41,54.61 v17.78,55.25 | v19.68,54.61 v20.32,55.25 | U2.J3 v20.32,56.52 v20.95,56.52 | v19.05,53.98 v18.41,54.61 | v19.68,53.34 v20.32,52.71 | v20.32,50.17 v19.68,49.53 | U2.A1 v17.14,45.72 v17.14,45.09 v17.78,45.09 | U2.A1 v18.41,45.72 | v18.41,45.72 U2.A2 v19.05,45.09 v18.41,45.09 | v17.78,45.09 v18.41,45.09 | U2.A1 v17.78,45.09 | v18.41,45.72 v18.41,45.09 | U2.B3 v20.32,46.36 U2.A3 v20.32,45.09 | U2.A4 v21.59,45.09 v22.86,45.09 U2.A5 | U2.A4 v21.59,46.36 | v21.59,46.36 U2.B4 | U2.B4 v21.59,47.62 | v21.59,47.62 U2.C4 | U2.C4 v21.59,48.9 | v21.59,48.9 U2.D4 | U2.D4 v21.59,50.17 U2.E4
  Top 0.61: v25.4,46.36 U2.B7 v25.4,45.09 U2.A7 | v26.67,45.09 U2.A8 v26.67,46.36 U2.B8 | v24.13,45.09 U2.A6 v24.13,46.36 U2.B6 v24.13,47.62 U2.C6 | U2.A5 v22.86,46.36 U2.B5 | U2.B5 v22.86,47.62 | v22.86,47.62 U2.C5 | U2.C5 v22.86,48.9 | v22.86,48.9 U2.D5 U2.D4 | U2.G4 v21.59,53.98 U2.H4 v21.59,55.25 U2.J4 | U2.G5 v22.86,53.98 | v22.86,53.98 U2.H5 | v22.86,55.25 U2.H5 | v22.86,55.25 U2.J5 | U2.J5 v22.86,56.52 | v22.86,56.52 v22.22,56.52 | v22.22,56.52 v22.22,55.88 v22.22,55.25 v22.22,54.61 v22.22,53.98 v22.22,53.34 | v20.95,53.34 v20.95,53.98 v20.95,54.61 v20.95,55.25 v20.95,55.88 v20.95,56.52 | v20.95,56.52 v21.59,56.52 v22.22,56.52 | v22.86,56.52 v22.22,56.52 | U2.J5 v22.86,56.52 | U2.J3 U2.J5 | v20.32,55.25 U2.J3 | v20.32,55.25 v22.86,55.25 | v22.86,55.25 U2.H5 | U2.H3 U2.H5 | v20.32,53.98 U2.H3 | v20.32,53.98 v22.86,53.98 | U2.G5 v22.86,53.98 | U2.G3 U2.G5 | v31.75,47.62 U2.C12 v32.38,48.26 v32.38,47.62 | v31.75,47.62 U2.B12 | U2.B12 v31.75,46.36 | v31.75,46.36 U2.A12 | U2.A12 v31.75,45.09 v32.38,45.09 v32.38,45.72 | v32.38,46.36 v32.38,45.72 | v32.38,46.99 v32.38,46.36 | v32.38,47.62 v32.38,46.99 | v32.38,47.62 v31.75,47.62 | v32.38,46.99 U2.B12 | v32.38,46.36 v31.75,46.36 | v32.38,45.72 U2.A12 | U2.A11 v30.48,45.09 | v32.38,52.07 U2.F12 v31.11,52.07 U2.F11 | U2.F11 v29.84,52.07 | v29.84,52.07 U2.F10 | U2.F10 v28.57,52.07 | v28.57,52.07 U2.F9 | U2.F9 v27.3,52.07 U2.F8 | U2.F9 v27.94,51.44 U2.E9 v28.57,50.8 | U2.E10 v28.57,50.8 | v29.84,50.8 U2.E10 | v29.84,50.8 U2.E11 v30.48,51.44 U2.F11 | v29.84,50.8 v29.84,51.44 v29.84,52.07 | U2.E10 v29.21,51.44 U2.F10 | v28.57,50.8 v28.57,51.44 v28.57,52.07 | v31.75,55.25 v32.38,55.25 | v31.75,55.25 U2.H12 v32.38,54.61 v32.38,55.25
  Top 0.61: v32.38,55.25 v32.38,55.88 U2.J12 v31.75,55.25 | v22.22,45.09 v22.22,49.53 | v21.59,48.9 v22.86,48.9 | U2.C4 U2.C5 | v21.59,47.62 v22.86,47.62 | U2.B4 U2.B5 | v21.59,46.36 22.73,46.36 | U2.A4 U2.A5 | J5.5 3.68,49.53 v6.35,49.53 | J5.4 3.3,57.91 v6.35,57.91 | v16.76,77.72 16.76,72.77 v17.14,72.39 v17.14,56.52 | v20.95,56.52 20.95,72.14 v21.21,72.39 21.34,72.52 v21.34,73.15 v21.34,77.72 | v17.14,55.25 v6.35,55.25 5.97,55.63 v0.89,55.63
  Bottom 0.203: SJ3.2 45.09,75.18 45.21,75.06 45.72,75.06 45.74,75.04 U10.7 45.74,73.77 46.18,73.33 46.18,73.28 | U1.4 56.94,24.72 57.02,24.64 | U1.3 56.95,24.07 57.02,24 | U1.2 56.97,23.42 57.02,23.37 | U1.1 56.86,22.77 56.9,22.73 | J8.2 57.82,22.57 v57.79,22.61 | SJ2.2 60.71,72.01
  Bottom 0.254: R8.2 19.94,30.24 19.94,31.62 | 19.94,31.62 J2.5 19.94,31.62 | 18.54,31.62 18.57,31.66 | C19.2 19.94,31.62 | R10.1 44.51,72.2 | v46.99,73.91 46.48,73.53 46.18,73.28 45.72,72.9 | v35.94,65.91 34.93,65.91 | v35.94,65.91 36.83,65.91 | v35.94,65.91 35.94,66.93 | v35.94,64.64 v35.94,65.91 | v27.3,40.64 26.42,40.64 | v27.3,40.64 28.19,40.64 | v27.3,40.64 27.3,39.62 | v27.3,40.64 27.3,41.66 | v62.87,66.67 62.89,66.65 65.28,66.65
  Bottom 0.305: v69.34,49.4 67.44,49.4 | v67.44,29.34 69.34,29.34 | v69.34,64.39 67.56,64.39 | v69.34,60.83 67.44,60.83 | v69.34,57.91 67.44,57.91 | v69.34,54.61 67.56,54.61 | v69.34,44.07 67.56,44.07 | v69.34,40.89 67.56,40.89 | v69.34,37.85 67.44,37.85 | v69.34,34.54 67.44,34.54 | v69.34,23.88 v67.31,23.88 | v67.31,21.21 69.21,21.21 v69.34,21.08 | v69.34,18.16 v67.31,18.16 | v67.18,14.35 v69.34,14.35
  Bottom 0.406: v28.19,1.02 28.19,0.64 28.45,0.64 | 28.45,0.64 28.57,0.64 28.57,5.46 arc-90 28.83,5.71 31.37,5.71 31.37,0.64 28.45,0.64 | 40.01,0.89 v40.39,0.89 | 40.01,0.89 40.01,0.64 | 40.01,0.89 40.01,5.46 39.75,5.71 37.34,5.71 37.21,5.59 37.21,0.64 40.13,0.64
  Bottom 0.61: C2.1 35.56,6.73 35.81,6.48 v36.45,6.48 37.85,5.08 37.85,3.81 J7.4 38.61,5.71 v38.35,5.97 v37.34,6.98 v37.34,10.03 v38.1,10.03 38.35,10.03 v38.74,10.41 38.74,13.84 v37.72,13.84 | v32.38,13.84 C7.2 | v37.72,13.84 C3.2 | v32.38,13.84 v33.53,15.75 v33.53,17.27 | v37.72,13.84 v36.58,15.75 v36.58,17.27 | v36.58,17.27 v36.58,50.29 | v36.58,50.29 v35.05,51.82 v33.53,51.82 32.64,51.82 v32.38,52.07 | v33.53,17.27 v33.53,48.26 | v33.53,48.26 v32.38,48.26 | v32.38,13.84 31.37,13.84 v31.37,10.41 v32,10.03 v32.77,10.03 v32.77,6.98 29.97,4.19 J7.5 | 35.05,10.03 v35.43,10.03 v35.43,9.27 35.05,8.89 | 35.05,8.89 v35.05,8.76 35.05,10.03 | 35.05,8.89 v34.67,9.27 v34.67,10.03 35.05,10.03 | v33.53,17.27 v33.53,48.26 | v36.58,17.27 v36.58,50.29 | v36.58,7.24 v36.58,8 36.96,8 36.96,7.24 v36.58,7.24
  Bottom 0.813: C5.2 36.77,73.21 35.05,74.93 TP4.1 32.96,72.96 C6.2 | 48.01,73.02 47.18,73.72 v46.99,73.91 | v46.36,73.53 44.7,73.53 | v47.62,73.53 49.53,73.53
  Bottom 1.27: v58.8,69.98 58.8,71.5 | U5.GP 58.8,67.31
  other vias: 53.85,52.07 55.12,53.34 43.94,54.1 43.94,53.21 43.94,52.07 45.21,52.07 44.58,52.58 54.48,52.71 44.2,64.26 44.2,65.02 43.94,66.42 45.09,66.42 44.45,65.79 54.74,65.28 53.72,66.29 54.74,66.29 54.23,65.79 45.21,48.77 43.94,48.77 44.58,48.13 43.94,47.5 43.94,46.61 53.72,48.77 54.74,48.77 54.74,46.61 54.74,47.75 54.23,48.26 45.21,34.54 43.94,34.54 44.58,35.05 43.94,35.56 43.94,36.58 53.85,34.54 55.12,34.54 54.48,35.18 55.12,35.81 55.12,36.7 40.77,6.98 32.77,14.48 37.34,14.48 36.96,15.11 33.15,15.11 33.53,16.51 36.58,16.51 18.41,52.71 14.35,51.56 13.59,51.56 12.83,51.56 12.06,51.56 11.3,51.56 10.54,51.56 9.78,51.56 9.02,51.56 8.26,51.56 7.49,51.56 6.35,50.93 16.26,55.25 15.49,55.25 14.73,55.25 13.97,55.25 13.21,55.25 12.45,55.25 11.68,55.25 10.92,55.25 10.16,55.25 9.4,55.25 8.64,55.25 7.87,55.25 7.11,55.25 6.73,55.88 15.88,55.88 7.11,56.52 15.11,55.88 14.35,55.88 13.59,55.88 12.83,55.88 12.06,55.88 11.3,55.88 10.54,55.88 9.78,55.88 9.02,55.88 8.26,55.88 7.49,55.88 7.87,56.52 16.26,50.93 15.49,50.93 14.73,50.93 13.97,50.93 13.21,50.93 12.45,50.93 11.68,50.93 10.92,50.93 10.16,50.93 9.4,50.93 8.64,50.93 7.87,50.93 7.11,50.93 5.46,51.05 7.49,50.29 22.22,48.9 22.22,48.26 22.22,47.62 22.22,46.99 22.22,46.36 22.22,45.72 20.95,57.28 20.95,58.04 20.95,58.8 20.95,60.33 20.95,61.09 20.95,61.85 20.95,62.61 20.95,63.37 20.95,64.14 20.95,64.9 20.95,65.66 20.95,66.42 20.95,67.18 20.95,67.94 20.95,68.71 20.95,69.47 20.95,70.23 20.95,70.99 21.84,72.64 24,72.39 17.14,57.28 17.14,58.04 17.14,58.8 17.14,59.56 17.14,60.33 17.14,61.09 17.14,61.85 17.14,62.61 17.14,63.37 17.14,64.14 17.14,64.9 17.14,65.66 17.14,66.42 17.14,67.18 17.14,67.94 17.14,68.71 17.14,69.47 17.14,70.23 17.14,70.99 16.38,72.52 13.97,72.39 21.59,57.66 21.59,58.42 21.59,59.18 21.59,59.94 21.59,60.71 21.59,61.47 21.59,62.23 21.59,62.99 21.59,63.75 21.59,64.52 21.59,65.28 21.59,66.04 21.59,66.8 21.59,67.56 21.59,68.33 21.59,69.09 21.59,69.85 21.59,70.61 21.59,71.37 22.35,71.37 22.48,72.39 16.51,57.66 16.51,58.42 16.51,56.9 16.51,59.18 16.51,59.94 16.51,60.71 16.51,61.47 16.51,62.23 16.51,62.99 16.51,63.75 16.51,64.52 16.51,65.28 16.51,66.04 16.51,66.8 16.51,67.56 16.51,68.33 16.51,69.09 16.51,69.85 16.51,70.61 16.51,71.37 15.75,71.37 15.49,72.39 16.51,56.13 15.62,56.52 15.88,57.28 14.73,56.52 15.24,57.15 15.88,58.04 15.24,57.79 14.48,57.15 13.97,56.52 33.53,18.03 33.53,18.8 33.53,20.83 36.58,18.03 36.58,18.8 36.58,19.56 36.58,41.28 33.53,41.28 33.53,42.67 36.58,42.67 33.53,44.07 36.58,44.07 36.58,44.83 36.58,46.23 33.53,45.97 33.02,45.47 33.53,46.74 33.53,47.5 36.58,46.86 36.58,47.62 36.58,48.26 36.58,49.53 36.07,50.8 35.56,51.31 34.29,51.82 33.02,52.32 32.89,51.44 33.91,52.45 34.67,52.45 35.43,52.45 35.94,51.94 36.45,51.44 36.96,50.93 37.21,50.29 37.21,49.53 37.21,48.01 37.21,47.24 37.21,46.48 37.85,47.62 37.85,46.86 37.85,48.26 37.85,46.23 33.02,47.88 33.02,47.12 33.02,46.36 46.99,73.15 45.72,73.91 45.72,73.15 48.26,73.91 48.26,73.15 31.37,13.46 31.37,12.7 31.37,11.94 31.37,11.18 32.77,9.27 32.77,8.51 32.77,7.75 32.26,6.48 38.74,13.46 38.74,12.7 38.74,11.94 38.74,11.18 37.34,9.27 37.34,8.51 37.34,7.75 38.1,6.86 32,8.89 32,8.13 32,7.37 31.5,6.86 31.5,9.4 16.76,76.96 16.76,76.2 16.76,75.44 16.76,74.68 16.76,73.91 16.76,73.15 21.34,76.96 21.34,76.2 21.34,75.44 21.34,74.68 21.34,73.91 1.65,55.63 2.41,55.63 3.17,55.63 3.94,55.63 4.7,55.63 5.46,55.63 1.65,51.05 2.41,51.05 3.17,51.05 3.94,51.05 4.7,51.05 8.26,50.29 36.45,1.02 36.45,1.78 36.45,2.54 36.45,3.3 36.45,4.06 36.45,4.83 32.26,1.02 32.26,1.78 32.26,2.54 32.26,3.3 32.26,4.06 32.26,4.83 31.62,5.21 40.39,1.65 40.39,2.41 40.39,3.17 40.39,3.94 40.39,4.7 40.39,5.46 39.88,5.97 39.12,5.97 28.19,1.78 28.19,2.54 28.19,3.3 28.19,4.06 28.19,4.83 28.19,5.59 28.7,6.1 29.46,6.1 30.23,6.1 30.99,6.1 1.52,59.56 2.29,59.56 3.05,59.56 3.81,59.56 4.57,59.56 5.33,59.56 6.35,57.15 6.35,58.67 5.97,59.31 0.89,47.12 1.65,47.12 2.41,47.12 3.17,47.12 3.94,47.12 4.7,47.12 5.46,47.12 6.1,47.37 6.35,48.01 6.35,48.77 13.33,72.52 12.83,73.02 12.83,73.79 12.83,74.55 12.83,75.31 12.83,76.07 12.83,76.83 24.77,72.64 25.27,73.15 25.27,73.91 25.27,74.68 25.27,75.44 25.27,76.2 25.27,76.96 5.71,3.81 5.71,74.93 54.86,59.18 54.74,41.66 53.98,50.17 52.2,50.42 50.55,51.05 48.51,51.05 48.51,49.78 50.55,49.78 46.99,50.42 43.31,41.78 42.04,41.4 40.64,41.78 39.37,41.4 38.1,41.91 43.05,39.62 43.05,37.59 41.28,39.62 39.5,39.62 40.39,38.48 42.16,38.48 41.28,37.47 40.39,36.2 42.29,36.2 41.28,34.93 39.37,6.98 67.49,34.54 42.16,5.71 44.07,5.71 45.97,5.71 47.88,5.71 50.29,5.71 43.18,3.81 45.09,3.81 46.99,3.81 48.9,3.81 50.8,3.81 41.4,3.81 42.16,1.91 44.07,1.91 45.97,1.91 47.88,1.91 49.78,1.91 43.18,0.76 45.09,0.76 46.99,0.76 48.9,0.76 50.8,0.76 52.71,0.76 54.61,0.76 56.52,0.76 52.71,5.71 62.23,0.76 55.88,6.98 53.98,6.98 13.33,59.05 13.97,58.42 12.7,58.42 13.33,57.79 12.06,57.79 11.43,58.42 10.79,57.79 10.16,58.42 8.89,58.42 7.62,58.42 8.26,57.79 9.53,57.79 8.89,57.15 10.16,57.15 11.43,57.15 12.7,57.15 9.53,56.64 10.79,56.64 12.06,56.64 13.21,56.64 13.72,57.15 14.22,57.79 14.61,59.05 15.88,59.05 15.11,58.42 15.88,60.96 13.33,60.96 10.79,60.96 8.26,60.96 5.71,60.96 3.17,60.96 0.76,60.96 14.61,62.23 12.06,62.23 9.53,62.23 6.98,62.23 4.45,62.23 1.91,62.23 6.98,59.69 9.53,59.69 12.06,59.69 15.88,63.5 13.33,63.5 10.79,63.5 8.26,63.5 5.71,63.5 3.17,63.5 0.76,63.5 14.61,64.77 12.06,64.77 9.53,64.77 6.98,64.77 4.45,64.77 1.91,64.77 15.88,65.91 13.33,66.04 10.79,66.04 8.26,66.04 5.71,66.04 3.17,66.04 0.76,66.04 1.91,67.31 4.45,67.31 7.11,67.31 9.53,67.31 12.06,67.31 14.61,67.31 13.33,68.58 15.88,68.58 10.79,68.58 8.26,68.58 5.71,68.58 3.17,68.58 0.76,68.58 1.91,69.85 4.45,69.85 6.98,69.85 9.53,69.85 12.06,69.85 14.61,69.85 13.33,71.12 10.79,71.12 8.26,71.12 5.71,71.12 3.17,71.12 0.76,71.12 1.91,72.39 0.76,73.66 1.91,74.93 0.76,76.2 1.91,77.47 9.53,72.39 11.94,72.39 8.89,77.47 0.76,77.98 11.43,77.47 15.24,50.17 13.97,50.17 12.7,50.17 11.43,50.17 10.16,50.17 15.24,48.9 13.97,48.9 12.7,48.9 11.43,48.9 10.16,48.9 8.89,48.9 7.62,48.9 9.02,50.17 15.24,47.62 12.7,47.62 10.16,47.62 7.62,47.62 13.97,46.36 11.43,46.36 8.89,46.36 6.48,46.36 15.24,45.09 12.7,45.09 10.16,45.09 7.62,45.09 5.08,45.09 2.54,45.09 13.97,43.82 11.43,43.82 8.89,43.82 6.35,43.82 3.81,43.82 1.27,43.82 2.54,42.55 5.08,42.55 7.62,42.55 10.16,42.55 12.7,42.55 15.24,42.55 13.97,41.28 11.43,41.28 8.89,41.28 6.35,41.28 3.81,41.28 1.27,41.28 2.54,40.01 5.08,40.01 7.62,40.01 10.16,40.01 12.7,40.01 15.24,40.01 13.97,38.74 11.43,38.74 8.89,38.74 6.35,38.74 3.81,38.74 1.27,38.74 5.08,37.47 2.54,37.47 1.27,36.2 2.54,34.93 1.27,33.66 2.54,32.38 1.27,31.11 2.54,29.84 1.27,28.57 2.54,27.3 1.27,5.71 2.54,4.45 1.27,3.17 5.08,29.84 3.81,28.57 5.08,27.3 6.35,28.57 7.62,29.84 7.62,27.3 8.89,28.57 10.16,29.84 10.16,27.3 11.43,28.57 12.7,29.84 12.7,27.3 11.43,31.11 8.89,31.11 10.16,32.38 8.89,33.66 11.43,33.66 12.7,32.38 10.16,34.93 11.43,36.07 8.89,36.07 12.7,34.93 11.43,5.71 10.16,4.45 8.89,5.71 8.89,3.17 11.43,3.17 10.16,1.91 8.89,0.76 11.43,0.76 6.35,0.76 3.81,0.76 13.97,0.76 16.51,0.76 19.05,0.76 16.51,3.17 16.51,5.71 16.51,28.57 15.24,27.3 17.78,27.3 17.78,29.84 15.24,29.84 16.51,30.48 19.05,28.57 19.05,30.48 19.05,5.71 20.32,27.3 22.86,27.3 21.59,28.57 21.59,5.71 22.86,4.45 22.86,1.91 21.59,3.17 21.59,0.76 24.13,0.76 26.67,0.76 25.4,1.91 24.13,3.17 26.67,3.17 25.4,4.45 26.67,5.71 24.13,5.71 25.4,27.3 24.13,28.57 22.86,29.84 25.4,29.84 26.67,28.57 25.4,31.88 24.13,30.73 27.94,29.84 30.48,9.53 29.08,28.57 30.48,7.11 27.94,27.3 30.48,32.38 30.61,34.93 31.75,15.88 31.75,38.74 32.77,17.14 31.24,37.47 40.26,46.36 42.55,46.36 41.28,47.62 42.55,48.9 40.01,48.9 41.28,50.17 43.82,50.17 42.55,51.44 40.01,51.44 41.28,52.71 42.55,53.98 40.01,53.98 38.74,52.58 38.74,50.17 37.47,53.98 36.2,52.71 37.47,51.44 34.93,53.98 36.2,55.25 33.66,55.25 34.93,56.39 33.4,52.96 23.5,63.5 23.5,60.96 22.22,62.23 24.77,62.23 22.22,64.77 24.77,64.77 26.04,63.5 27.3,64.77 26.04,66.04 23.5,66.04 24.77,67.31 22.22,67.31 23.5,68.58 22.22,69.85 24.77,69.85 26.04,68.58 27.3,67.31 28.57,66.04 28.57,68.58 27.3,69.85 29.84,69.85 28.57,71.12 26.04,71.12 23.5,71.12 27.3,72.39 29.84,72.39 29.84,67.31 31.11,66.04 29.21,64.77 32.26,64.77 33.02,67.31 30.48,64.77 30.99,68.58 37.47,64.64 36.96,67.82 34.67,64.64 40.01,64.64 40.01,67.31 40.01,70.1 40.01,72.39 41.28,71.12 41.28,68.33 41.91,70.23 43.31,71.5 42.55,72.39 43.82,73.66 43.82,76.2 40.01,77.47 37.47,77.47 34.93,77.47 32.38,77.47 29.84,77.47 27.3,77.47 32.38,74.93 31.11,76.2 37.47,74.93 52.71,67.31 50.42,67.31 47.62,67.31 42.8,64.39 42.8,66.17 44.58,67.31 53.98,77.98 51.44,77.98 17.78,42.55 19.05,41.28 17.78,40.01 19.05,38.74 16.64,38.23 23.75,41.78 24.13,38.74 25.78,39.5 25.53,42.55 25.4,37.47 26.67,38.74 29.21,38.74 28.07,39.62 27.94,37.47 26.16,41.4 21.59,41.28 21.59,38.74 21.59,43.43 20.32,42.55 20.32,40.01 20.32,38.61 25.15,34.93 25.15,33.27 23.62,36.7 24,43.43 58.29,69.34 59.31,69.34 59.31,70.61 58.29,70.61 59.31,68.07 58.29,68.07 58.8,68.71 68.33,69.72 68.33,65.79 68.33,59.31 68.33,53.09 68.33,45.72 68.33,39.37 68.33,33.02 68.33,19.3 68.33,12.95 68.33,8.89 67.44,10.92 69.21,10.92 67.31,16.13 69.34,16.13 67.44,27.81 69.21,27.81 69.21,30.99 67.44,30.99 69.21,29.34 69.34,36.2 69.34,42.55 69.34,47.75 69.34,50.93 69.34,56.26 69.34,62.61 67.31,67.82 69.34,67.82 67.49,36.2 67.49,37.85 67.49,40.89 67.49,42.55 67.49,44.07 67.49,47.75 67.49,49.4 67.49,50.93 67.49,54.61 67.49,56.26 67.49,57.91 67.49,60.83 67.49,62.61 67.49,64.39 68.33,49.38 68.33,29.36 1.27,26.04 3.81,26.04 6.35,26.04 5.08,24.77 2.54,24.77 1.27,23.5 3.81,23.5 6.35,23.5 7.62,24.77 8.89,26.04 11.43,26.04 11.43,23.5 11.43,20.95 10.16,24.77 10.16,22.22 8.89,23.5 8.89,20.95 7.62,22.22 6.35,20.95 5.08,22.22 3.81,20.95 2.54,22.22 1.27,20.95 12.7,24.77 12.7,22.22 12.7,19.68 10.16,19.68 7.62,19.68 5.08,19.68 2.54,19.68 11.43,18.41 8.89,18.41 6.35,18.41 3.81,18.41 1.27,18.41 12.7,17.14 10.16,17.14 7.62,17.14 5.08,17.14 2.54,17.14 11.43,15.88 8.89,15.88 6.35,15.88 3.81,15.88 1.27,15.88 12.7,14.61 10.16,14.61 7.62,14.61 5.08,14.61 2.54,14.61 11.43,13.33 8.89,13.33 6.35,13.33 3.81,13.33 1.27,13.33 12.7,12.06 10.16,12.06 7.62,12.06 5.08,12.06 2.54,12.06 11.43,10.79 8.89,10.79 6.35,10.79 3.81,10.79 1.27,10.79 12.7,9.53 10.16,9.53 7.62,9.53 5.08,9.53 2.54,9.53 11.43,8.26 8.89,8.26 6.35,8.26 3.81,8.26 1.27,8.26 12.7,6.98 10.16,6.98 7.62,6.98 5.08,6.98 2.54,6.98 16.51,26.04 19.05,26.04 21.59,26.04 24.13,26.04 26.67,26.04 29.21,26.04 31.62,28.57 30.48,27.3 31.75,26.04 30.48,24.77 27.94,24.77 25.4,24.77 22.86,24.77 20.32,24.77 17.78,24.77 15.24,24.77 16.51,23.5 19.05,23.5 21.59,23.5 24.13,23.5 26.67,23.5 29.21,23.5 31.75,23.5 15.24,22.22 17.78,22.22 20.32,22.22 22.86,22.22 25.4,22.22 27.94,22.22 16.51,20.95 19.05,20.95 21.59,20.95 24.13,20.95 26.67,20.95 29.21,20.95 30.48,22.22 31.75,20.95 30.48,19.68 27.94,19.68 25.4,19.68 22.86,19.68 20.32,19.68 17.78,19.68 15.24,19.68 16.51,18.41 19.05,18.41 21.59,18.41 24.13,18.41 26.67,18.41 29.21,18.41 31.75,18.41 15.24,17.14 17.78,17.14 20.32,17.14 22.86,17.14 25.4,17.14 27.94,17.14 30.48,17.14 29.21,15.88 26.67,15.88 24.13,15.88 21.59,15.88 19.05,15.88 16.51,15.88 15.24,14.61 17.78,14.61 20.32,14.61 22.86,14.61 25.4,14.61 27.94,14.61 30.48,14.61 29.21,13.33 26.67,13.33 24.13,13.33 21.59,13.33 19.05,13.33 16.51,13.33 15.24,12.06 17.78,12.06 20.32,12.06 22.86,12.06 25.4,12.06 27.94,12.06 30.48,12.06 29.21,10.79 26.67,10.79 24.13,10.79 21.59,10.79 19.05,10.79 16.51,10.79 15.24,9.53 17.78,9.53 20.32,9.53 22.86,9.53 25.4,9.53 27.94,9.53 29.21,8.26 26.67,8.26 24.13,8.26 21.59,8.26 19.05,8.26 16.51,8.26 15.24,6.98 17.78,6.98 20.32,6.98 22.86,6.98 25.4,6.98 27.94,6.98 33.53,23.37 33.53,25.91 33.53,28.45 33.53,29.72 33.53,30.99 33.53,32.26 33.53,33.53 33.53,34.8 33.53,36.07 33.53,37.34 33.53,38.61 33.53,39.75 36.7,20.83 36.7,22.1 36.7,23.37 36.7,24.64 36.7,25.91 36.7,27.18 36.7,28.45 36.7,29.72 36.7,30.99 36.7,32.26 36.7,33.53 36.7,34.8 36.7,36.07 36.7,37.34 36.7,38.61 36.7,39.75 39.37,34.93 37.21,35.31 38.48,36.2 39.37,37.47 38.48,38.74 37.21,36.7 38.1,32.38 40.64,32.38 43.18,32.38 45.72,32.38 48.26,32.38 50.8,32.38 39.37,31.11 41.91,31.11 44.45,31.11 46.99,31.11 49.53,31.11 52.07,31.11 50.8,29.84 48.26,29.84 45.72,29.84 43.18,29.84 40.64,29.84 38.1,29.84 39.37,28.57 41.91,28.57 44.45,28.57 46.99,28.57 49.53,28.57 52.07,28.57 38.1,27.3 40.64,27.3 43.18,27.3 45.72,27.3 48.26,27.3 50.8,27.3 39.37,26.04 41.91,26.04 44.45,26.04 46.99,26.04 49.53,26.04 52.07,26.04 50.8,24.77 48.26,24.77 45.72,24.77 43.18,24.77 40.64,24.77 38.1,24.77 39.37,23.5 41.91,23.5 44.45,23.5 46.99,23.5 49.53,23.5 52.07,23.5 38.1,22.22 40.64,22.22 43.18,22.22 45.72,22.22 48.26,22.22 50.8,22.22 52.07,20.95 49.53,20.95 46.99,20.95 44.45,20.95 41.91,20.95 39.37,20.95 38.1,19.68 40.64,19.68 43.18,19.68 45.72,19.68 48.26,19.68 50.8,19.68 52.07,18.41 49.53,18.41 46.99,18.41 44.45,18.41 41.91,18.41 39.37,18.41 38.1,17.14 40.64,17.14 43.18,17.14 45.72,17.14 48.26,17.14 50.8,17.14 52.07,15.88 49.53,15.88 46.99,15.88 44.45,15.88 41.91,15.88 39.37,15.88 38.1,14.61 40.64,14.61 43.18,14.61 45.72,14.61 48.26,14.61 50.8,14.61 41.91,13.33 44.45,13.33 46.99,13.33 49.53,13.33 52.07,13.33 54.61,13.33 55.88,12.06 53.34,12.06 50.8,12.06 48.26,12.06 45.72,12.06 43.18,12.06 41.91,10.79 44.45,10.79 46.99,10.79 49.53,10.79 52.07,10.79 54.61,10.79 55.88,9.53 53.34,9.53 50.8,9.53 48.26,9.53 45.72,9.53 43.18,9.53 40.64,12.06 40.64,9.53 39.37,10.79 41.91,8.26 39.37,8.26 44.45,8.26 46.99,8.26 49.53,8.26 52.07,8.26 54.61,8.26 50.8,6.98 48.26,6.98 45.72,6.98 43.18,6.98 39.5,13.33 57.15,8.26 57.15,10.79 57.15,13.33 58.42,12.06 59.69,10.79 58.42,9.53 58.42,6.98 57.15,5.71 58.42,4.45 57.15,3.17 58.42,1.91 59.69,8.26 59.69,5.71 59.69,3.17 59.69,0.76 55.88,14.61 53.34,14.61 53.34,17.14 54.61,15.88 53.34,19.68 55.88,19.68 54.61,20.95 53.34,22.22 53.34,24.77 53.34,27.3 53.34,29.84 54.61,18.41 55.88,17.14 57.15,18.41 59.69,18.41 62.23,18.41 58.42,17.14 60.96,17.14 63.5,17.14 57.15,15.88 59.69,15.88 62.23,15.88 58.42,14.61 60.96,14.61 63.5,14.61 59.69,13.33 62.23,13.33 60.96,12.06 63.5,12.06 62.23,10.79 64.77,10.79 60.96,9.53 63.5,9.53 66.04,9.53 62.23,8.26 64.77,8.26 67.31,8.26 60.96,6.98 63.5,6.98 66.04,6.98 64.77,5.71 66.04,4.45 64.77,3.17 66.04,1.91 64.77,0.76 68.58,6.98 69.85,8.26 71.12,6.98 72.39,8.26 73.53,6.98 72.39,5.71 71.12,4.45 72.39,3.17 71.12,1.91 72.39,0.76 69.85,0.76 67.31,0.76 73.53,1.91 73.53,4.45 73.53,9.53 72.39,10.79 73.53,12.06 73.53,14.61 73.53,17.14 73.53,19.68 73.53,22.22 73.53,24.77 73.53,27.3 73.53,29.84 72.39,28.57 71.12,29.84 71.12,27.3 49.53,33.53 47.12,33.53 54.61,31.11 55.88,29.84 57.15,31.11 54.61,28.57 57.15,28.57 55.88,27.3 54.61,26.04 57.15,26.04 58.42,27.3 58.42,29.84 59.69,31.11 59.69,28.57 60.96,27.3 59.69,26.04 62.23,26.04 62.23,28.57 60.96,29.84 62.23,31.11 63.5,29.84 64.77,31.11 66.04,29.84 64.77,28.57 63.5,27.3 66.04,27.3 63.5,19.68 62.23,20.95 63.5,21.84 55.88,51.44 55.88,46.74 61.85,46.74 61.47,48.01 59.94,46.74 58.04,46.74 58.55,48.39 58.8,50.93 65.79,50.04 65.79,51.44 61.47,51.56 63.12,49.91 64.26,50.67 65.79,47.75 64.01,47.62 58.17,59.18 57.02,59.18 55.88,59.18 55.75,49.91 54.48,51.05 60.2,64.14 56.64,64.14 58.29,64.14 61.85,63.5 63.12,63.75 63.88,65.15 64.14,67.69 62.87,68.83 64.14,69.85 65.28,68.71 66.42,69.85 66.42,67.82 48.9,77.98 56.52,77.98 59.05,77.98 61.6,77.98 64.14,77.98 66.67,77.98 69.21,77.98 50.17,76.83 51.44,75.56 52.71,76.96 55.25,76.96 56.52,75.56 59.05,75.56 57.79,76.83 57.79,74.3 59.05,73.02 56.52,73.02 52.07,72.77 53.98,72.62 60.33,76.83 65.41,76.83 65.41,74.3 64.14,73.15 66.67,73.02 71.75,73.02 73.02,74.3 70.61,74.3 71.75,75.06 70.48,76.83 73.02,71.75 73.53,73.02 37.21,21.46 37.21,20.19 37.21,22.73 37.21,24 37.21,25.27 37.21,26.54 37.21,27.81 37.21,29.08 37.21,30.35 37.21,31.62 37.21,32.89 37.21,34.04 37.21,37.97 37.21,39.24 32.89,39.24 32.89,37.97 33.02,36.7 33.02,35.43 33.02,34.16 33.02,32.89 33.02,31.62 33.02,30.35 33.02,29.08 33.53,27.18 33.02,27.81 33.02,26.54 33.53,24.64 33.02,25.27 33.02,24 33.53,22.1 33.02,22.73 33.02,21.46 33.53,19.81 33.02,20.32 33.02,19.3 41.91,33.66 39.37,33.66
  pour Top (no thermals): 54.48,54.48 54.48,53.09 54.36,52.96 52.83,52.96 52.83,51.82 55.37,51.82 55.37,54.48
  pour Top (no thermals): 44.58,54.48 44.58,52.96 44.7,52.83 46.23,52.83 46.23,51.82 43.82,51.82 43.69,51.94 43.69,54.48
  pour Top (no thermals): 46.23,66.67 46.23,65.53 44.83,65.53 44.58,65.28 44.58,63.88 43.69,63.88 43.69,66.55 43.82,66.67
  pour Top (no thermals): 52.83,66.55 52.83,65.53 54.36,65.53 54.48,65.41 54.48,63.88 54.99,64.39 54.99,66.42 54.86,66.55
  pour Top (no thermals): 54.48,36.96 54.48,35.56 54.36,35.43 52.83,35.43 52.83,34.29 55.37,34.29 55.37,36.96
  pour Top (no thermals): 44.58,36.96 44.58,35.43 44.7,35.31 46.23,35.31 46.23,34.29 43.82,34.29 43.69,34.42 43.69,36.96
  pour Top (no thermals): 52.83,49.02 52.83,48.01 54.36,48.01 54.48,47.88 54.48,46.36 54.99,46.36 54.99,48.9 54.86,49.02
  pour Top (no thermals): 46.23,49.02 46.23,47.88 44.83,47.88 44.58,47.62 44.58,46.23 43.69,46.23 43.69,48.9 43.82,49.02
  pour Route3 (isolate 0.254): 0.38,78.36 63.12,78.36 63.12,71.75 68.58,71.75 68.58,28.07 63.12,28.07 63.12,0.38 0.38,0.38
  pour Top (no thermals): 27.94,0 27.94,5.71 arc-90 28.57,6.35 31.11,6.35 31.62,5.84 37.85,5.84 38.23,6.22 40.13,6.22 arc-90 40.64,5.71 40.64,0
  pour Bottom (no thermals): 0,59.82 5.46,59.82 arc-90 6.6,58.67 6.6,57.15 5.71,56.26 5.71,50.55 6.6,49.66 6.6,47.88 arc-90 5.59,46.86 0,46.86
  pour Bottom (no thermals): 12.57,78.74 12.57,72.9 arc90 13.33,72.14 24.64,72.14 arc90 25.53,73.02 25.53,78.74
  pour Bottom (isolate 0.254, rank 2): 74.04,78.49 0.25,78.49 0.25,0.25 74.04,0.25
  pour Top (isolate 0.254, rank 2): 0.25,78.49 74.04,78.49 74.04,0.25 0.25,0.25
  pour Route2 (isolate 0.381): 0.25,78.49 63.25,78.49 63.25,72.64 arc90 64.01,71.88 68.58,71.88 68.58,27.94 64.14,27.94 arc90 63.25,27.05 63.25,0.25 0.25,0.25
  pour Bottom (no thermals): 44.07,1.91 50.29,1.91 50.29,5.71 44.07,5.71
  pour Bottom: 56.64,22.35 56.64,25.15 59.31,25.15 59.31,22.35
LO
  Top 0.508: U2.J2 L5.2
MIX_EN
  Top 0.152: U2.F4 20.95,51.44 20.95,49.15 20.7,48.9 19.94,48.9 19.68,48.64 19.68,37.72 19.43,37.47 15.49,37.47 15.11,37.08 9.73,37.08 9.47,36.83 9.47,35.56 8.59,34.67 5.86,34.67 J6.3
MODE
  Top 0.152: J2.4 22.61,33.66 22.99,34.04 22.99,43.69 23.5,44.2 24.26,44.2 24.77,44.7 24.77,47.62 U2.C7
  Bottom 0.254: J2.4 21.95,33.63 19.98,33.63 J2.3
N$1
  Bottom 0.406: T2.4 33.78,8.89 34.29,8.38 C1.2
N$2
  Bottom 0.406: T2.5 36.32,9.02 35.56,8.26 C2.2
N$3
  Bottom 0.813: 35.05,11.3 35.05,14.22
  pour Bottom (no thermals): 34.54,14.61 34.54,13.84 34.8,13.59 34.8,11.81 34.67,11.68 32,11.68 32,10.79 38.1,10.79 38.1,11.68 35.43,11.68 35.31,11.81 35.31,13.59 35.56,13.84 35.56,14.61
N$4
  Bottom 0.406: J7.1 34.42,3.05 34.29,3.17 C1.1
N$5  (via drill 0.25)
  Top 0.127: v23.5,58.93 23.5,59.56 23.88,59.94 24,59.94 27.81,63.75 42.37,63.75 42.67,63.45 43.49,63.45
  Top 0.152: R17.1 43.49,63.45 43.5,63.43 U3.4 | v24.77,50.17 U2.D6
  Route2 0.127: v24.77,50.17 24.77,50.67 24,51.44 24,52.32 23.5,52.83 v23.5,58.93
N$6
  Bottom 0.305: R5.1 34.54,16.32 34.54,15.49 C4.2 33.66,14.57 33.66,14.35 R2.1 33.78,14.29 T2.3
N$7
  Bottom 0.305: R4.1 35.56,16.32 35.56,15.49 C4.1 36.32,14.7 36.32,14.29 | 36.32,14.29 36.32,14.22 | 36.32,14.29 R1.1 | T2.1 36.32,14.29
N$8
  Top 0.152: J6.2 6.84,37.22 7.34,37.72 R36.1
N$9
  Top 0.406: 13.97,53.29 13.97,53.3 C43.1 | 14.53,53.29 14.62,53.3 L1.1
  Top 0.508: C43.1 9.69,53.3 9.65,53.34 C37.1 C37.2 | C37.2 8.76,53.34 | J5.1 C37.2 | 13.97,53.29 14.53,53.29
N$10
  Bottom 0.203: U10.8 46.24,76.31 46.23,76.33 R12.1 46.29,76.52 46.23,76.58 SJ3.1
N$11
  Bottom 0.254: R7.1 23.74,31.62 21.97,31.62 | 21.97,31.62 21.97,31.64 J2.6 | R8.1 21.97,30.24 21.97,31.62
N$12  (via drill 0.25)
  Top 0.152: U2.F5 22.73,52.07 v22.22,52.58
  Bottom 0.152: R28.1 22.48,52.58 v22.22,52.58
N$13
  Top 0.305: C39.1 19.05,59.56
  Top 0.508: L5.1 19.05,59.56 J9.1
N$14  (via drill 0.25)
  Top 0.152: U4.29 53.28,37.85
  Top 0.203: v63.25,34.42 59.94,34.42 56.52,37.85 53.28,37.85
  Bottom 0.203: J1.48 64.48,33.62 64.26,33.4 63.75,33.4 63.25,33.91 v63.25,34.42
N$15
  Bottom 0.254: R6.2 21.7,37.35 21.95,37.1 J2.2 21.95,35.67 21.97,35.69 21.98,35.68 R11.2
N$16  (via drill 0.25)
  Top 0.152: U4.28 53.92,37.41 53.98,37.34
  Top 0.203: v64.01,34.04 63.75,34.04 63.5,33.78 59.56,33.78 56.01,37.34 53.98,37.34
  Bottom 0.203: J1.50 64.22,34.12 v64.01,34.04
N$17  (via drill 0.25)
  Top 0.152: 53.47,38.86 53.47,38.91 U4.31
  Top 0.203: v63.25,35.94 60.33,35.94 57.4,38.86 53.47,38.86
  Bottom 0.203: J1.54 64.45,35.12 64.26,34.93 63.75,34.93 63.25,35.43 v63.25,35.94
N$18  (via drill 0.25)
  Top 0.152: U4.30 53.26,38.41 | U4.30 | 53.85,38.35 53.77,38.41 U4.30
  Top 0.203: v64.01,35.43 63.88,35.31 60.07,35.31 57.02,38.35 53.85,38.35
  Bottom 0.203: J1.56 64.19,35.62 v64.01,35.43
N$19  (via drill 0.25)
  Top 0.152: 53.47,39.88 53.47,39.91 U4.33
  Top 0.203: v63.25,37.47 60.96,37.47 58.42,39.88 53.47,39.88
  Bottom 0.203: J1.60 64.43,36.62 64.26,36.45 63.75,36.45 63.25,36.96 v63.25,37.47
N$20  (via drill 0.25)
  Top 0.152: 53.27,39.4 53.26,39.4 | U4.32 53.27,39.4 | 53.98,39.37 53.87,39.4 53.27,39.4
  Top 0.203: v64.01,37.08 63.75,36.83 60.58,36.83 58.04,39.37 53.98,39.37
  Bottom 0.203: J1.62 64.17,37.12 v64.01,37.08
N$21  (via drill 0.25)
  Top 0.152: 53.34,40.89 53.34,40.91 U4.35
  Top 0.203: v63.25,38.99 61.21,38.99 59.31,40.89 53.34,40.89
  Bottom 0.203: J1.66 64.41,38.12 64.26,37.97 63.75,37.97 63.25,38.48 v63.25,38.99
N$22  (via drill 0.25)
  Top 0.152: U4.34 53.75,40.41 53.85,40.39
  Top 0.203: v64.01,38.61 63.75,38.35 60.96,38.35 58.93,40.39 53.85,40.39
  Bottom 0.203: J1.68 64.15,38.62 v64.01,38.61
N$23  (via drill 0.25)
  Top 0.152: U4.39 53.28,42.8 53.34,42.8 53.47,42.93
  Top 0.203: v63.25,40.51 61.6,40.51 59.18,42.93 53.47,42.93
  Bottom 0.203: J1.72 64.39,39.62 64.26,39.5 63.75,39.5 63.25,40.01 v63.25,40.51
N$24  (via drill 0.25)
  Top 0.152: U4.38 53.29,42.39 53.82,42.39 53.85,42.42
  Top 0.203: v64.01,40.13 63.75,39.88 61.34,39.88 58.8,42.42 53.85,42.42
  Bottom 0.203: J1.74 64.12,40.12 v64.01,40.13
N$25  (via drill 0.25)
  Top 0.152: U4.41 54.38,43.92 54.36,43.94
  Top 0.203: v63.25,41.91 62.61,41.91 60.58,43.94 54.36,43.94
  Bottom 0.203: J1.78 64.49,41.12 64.26,40.89 63.75,40.89 63.25,41.4 v63.25,41.91
N$26  (via drill 0.25)
  Top 0.152: 53.34,43.43 53.34,43.41 U4.40
  Top 0.203: v64.01,41.53 63.75,41.28 62.23,41.28 60.07,43.43 53.34,43.43
  Bottom 0.203: J1.80 64.23,41.62 v64.01,41.53
N$27  (via drill 0.25)
  Top 0.152: U4.43 53.77,44.91 53.72,44.96
  Top 0.203: v63.12,43.56 62.74,43.56 61.34,44.96 53.72,44.96
  Bottom 0.203: J1.84 64.47,42.62 64.26,42.42 63.75,42.42 63.12,43.05 v63.12,43.56
N$28  (via drill 0.25)
  Top 0.152: 53.34,44.45 53.34,44.41 U4.42
  Top 0.203: v64.01,43.05 63.5,43.05 63.37,42.93 62.61,42.93 61.09,44.45 53.34,44.45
